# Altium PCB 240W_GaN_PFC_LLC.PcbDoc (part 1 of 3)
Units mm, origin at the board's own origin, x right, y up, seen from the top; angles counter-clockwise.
Board outline 105 x 71.8 mm, 4 copper layers (Top Layer, Layer 1, Layer 2, Bottom Layer), stack 1.787 mm thick; 165 components, 88 nets, 549 pads, 326 vias.
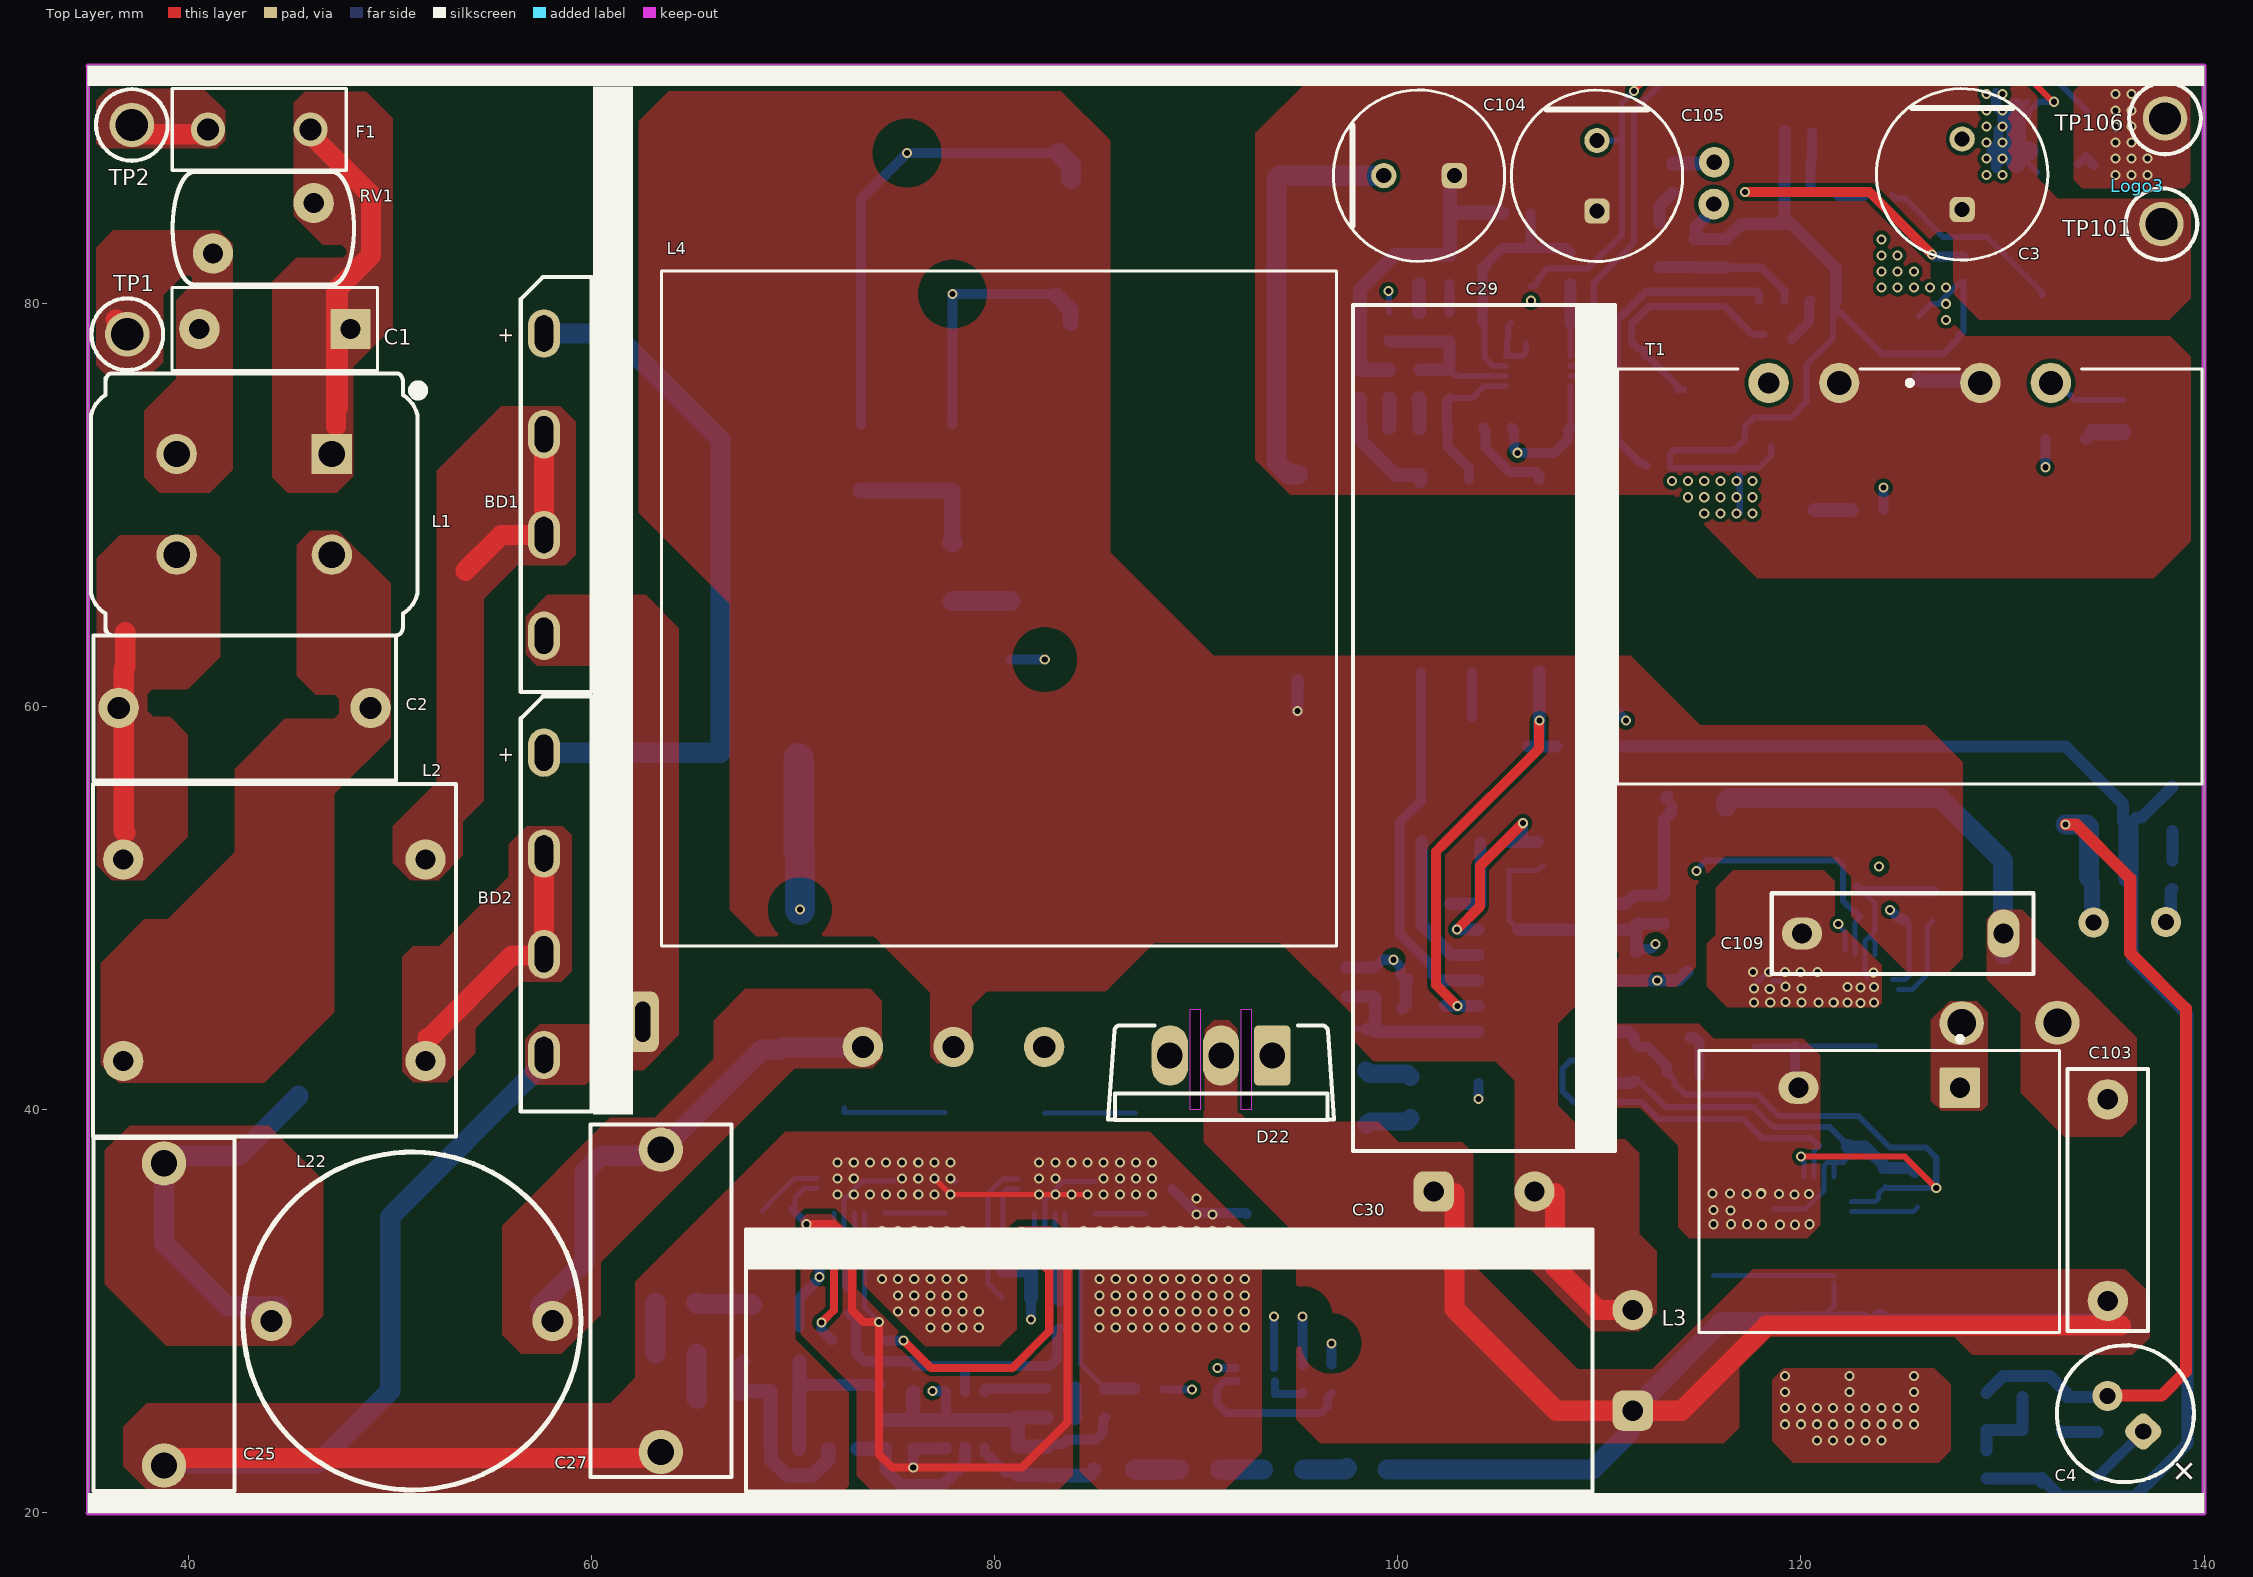
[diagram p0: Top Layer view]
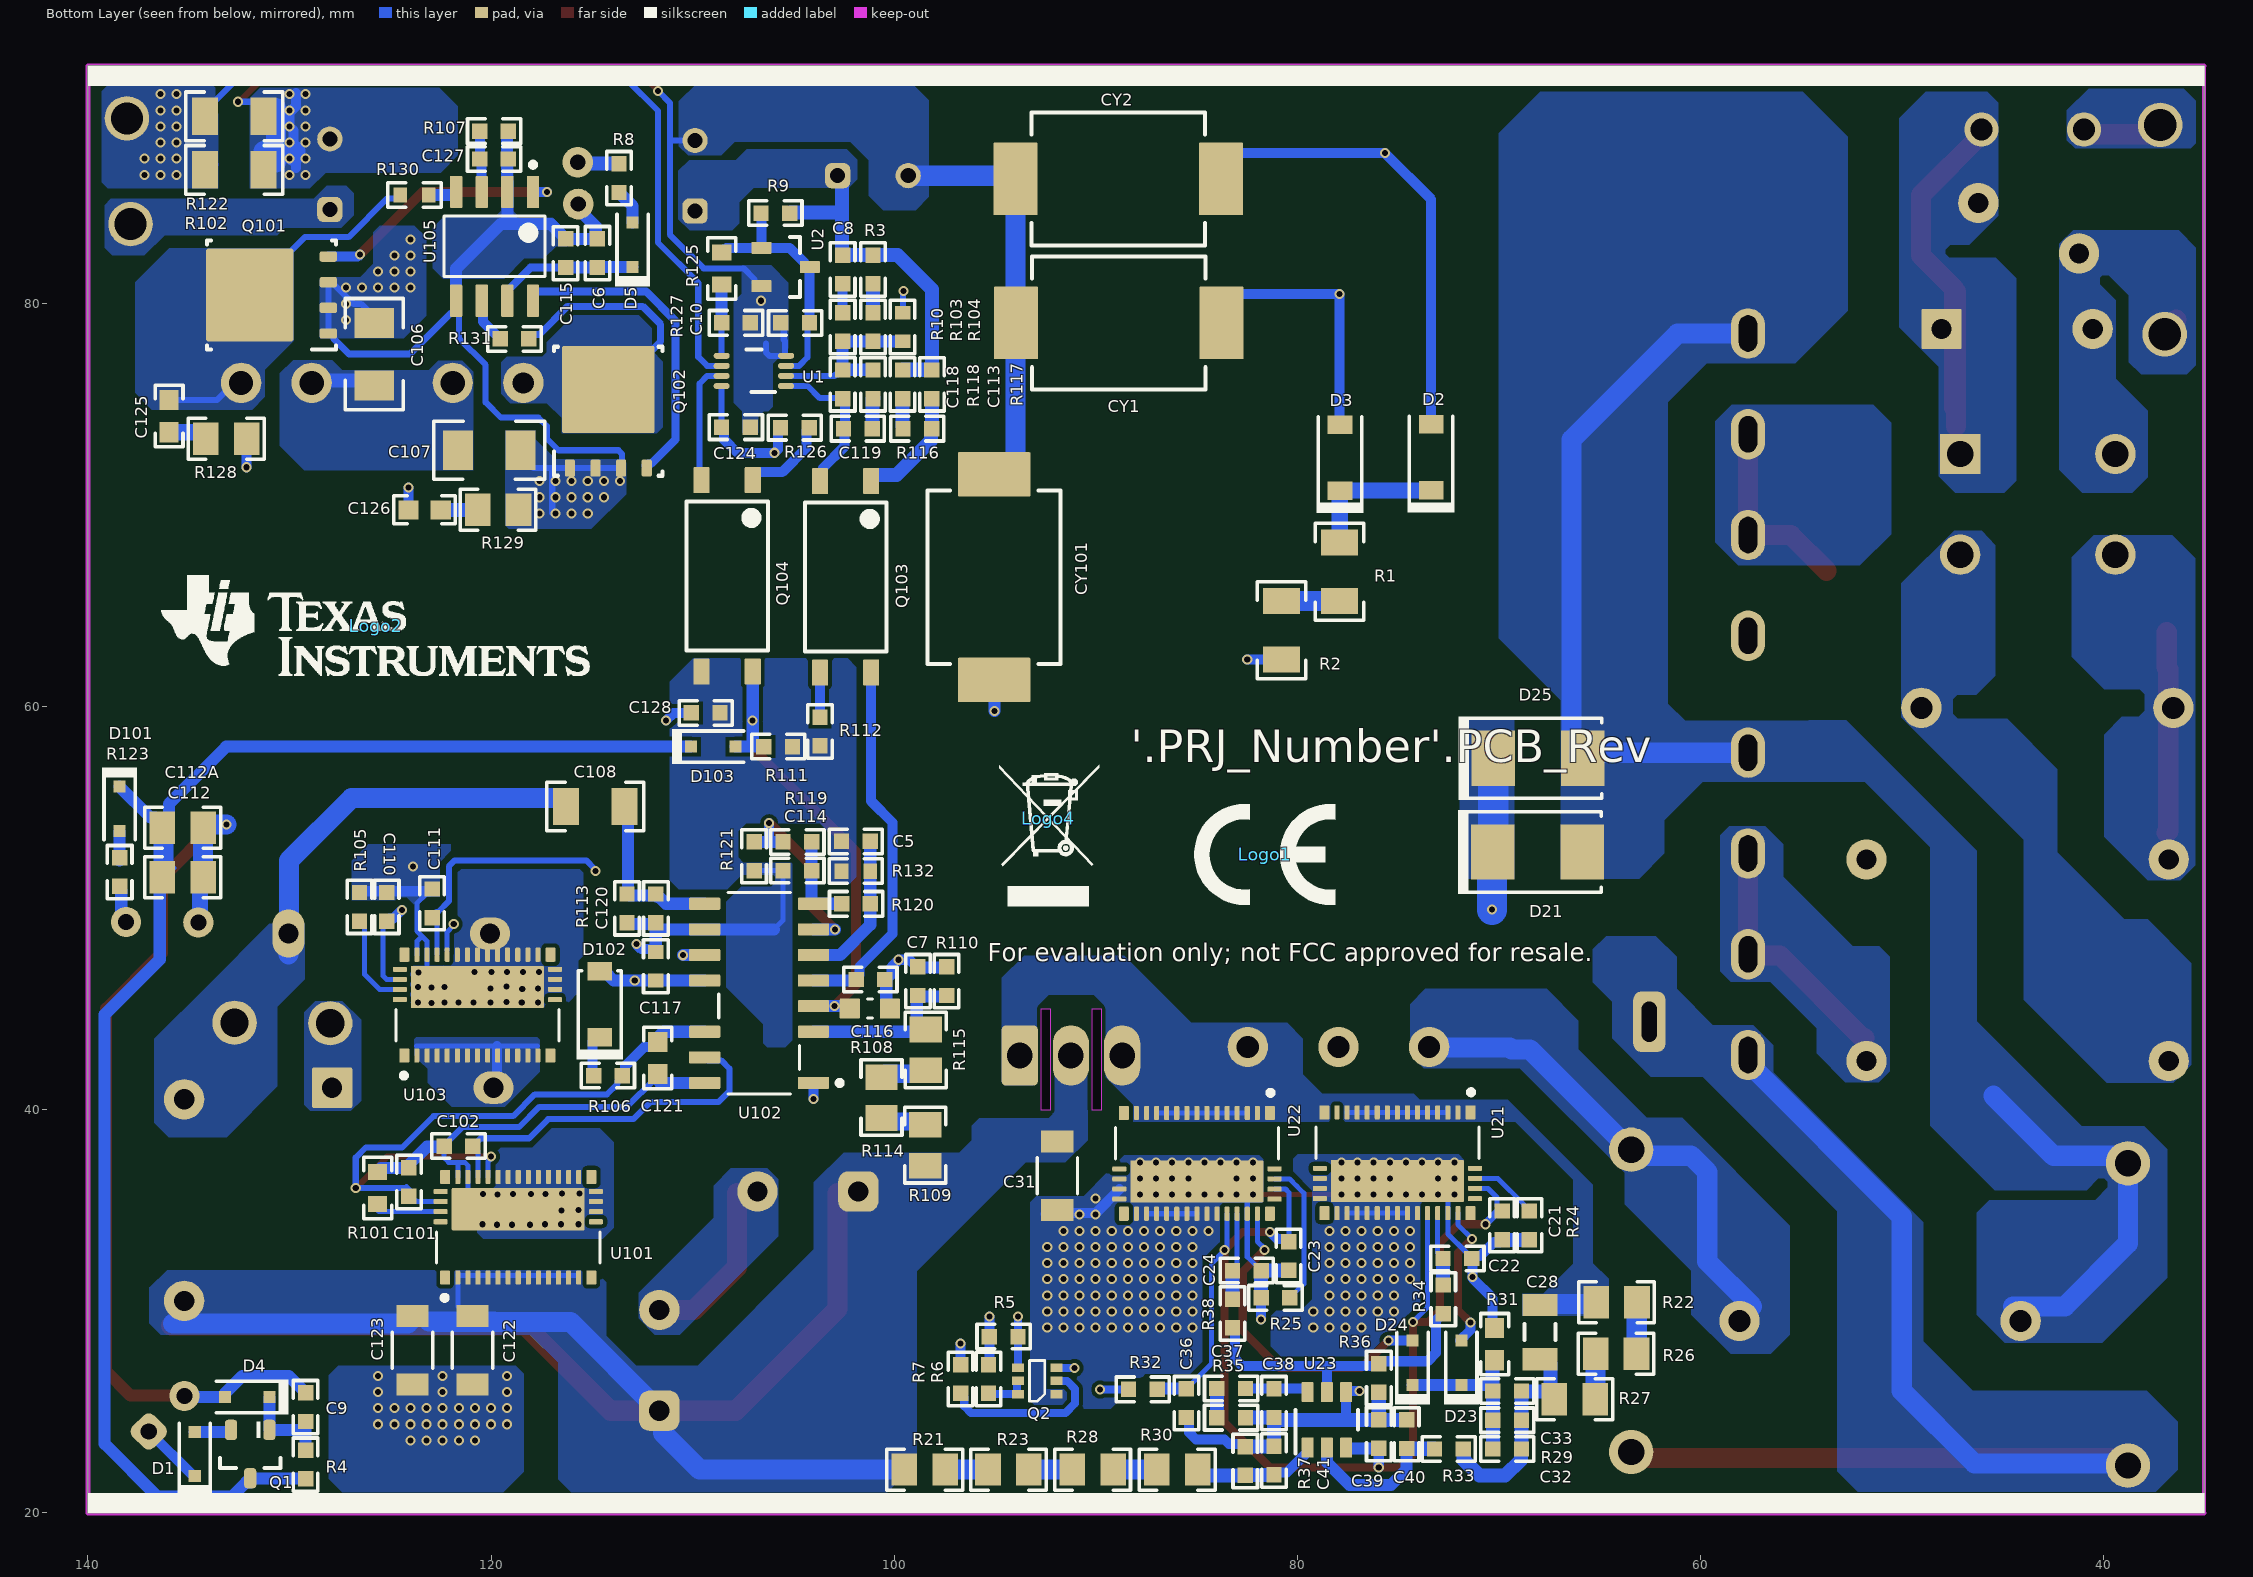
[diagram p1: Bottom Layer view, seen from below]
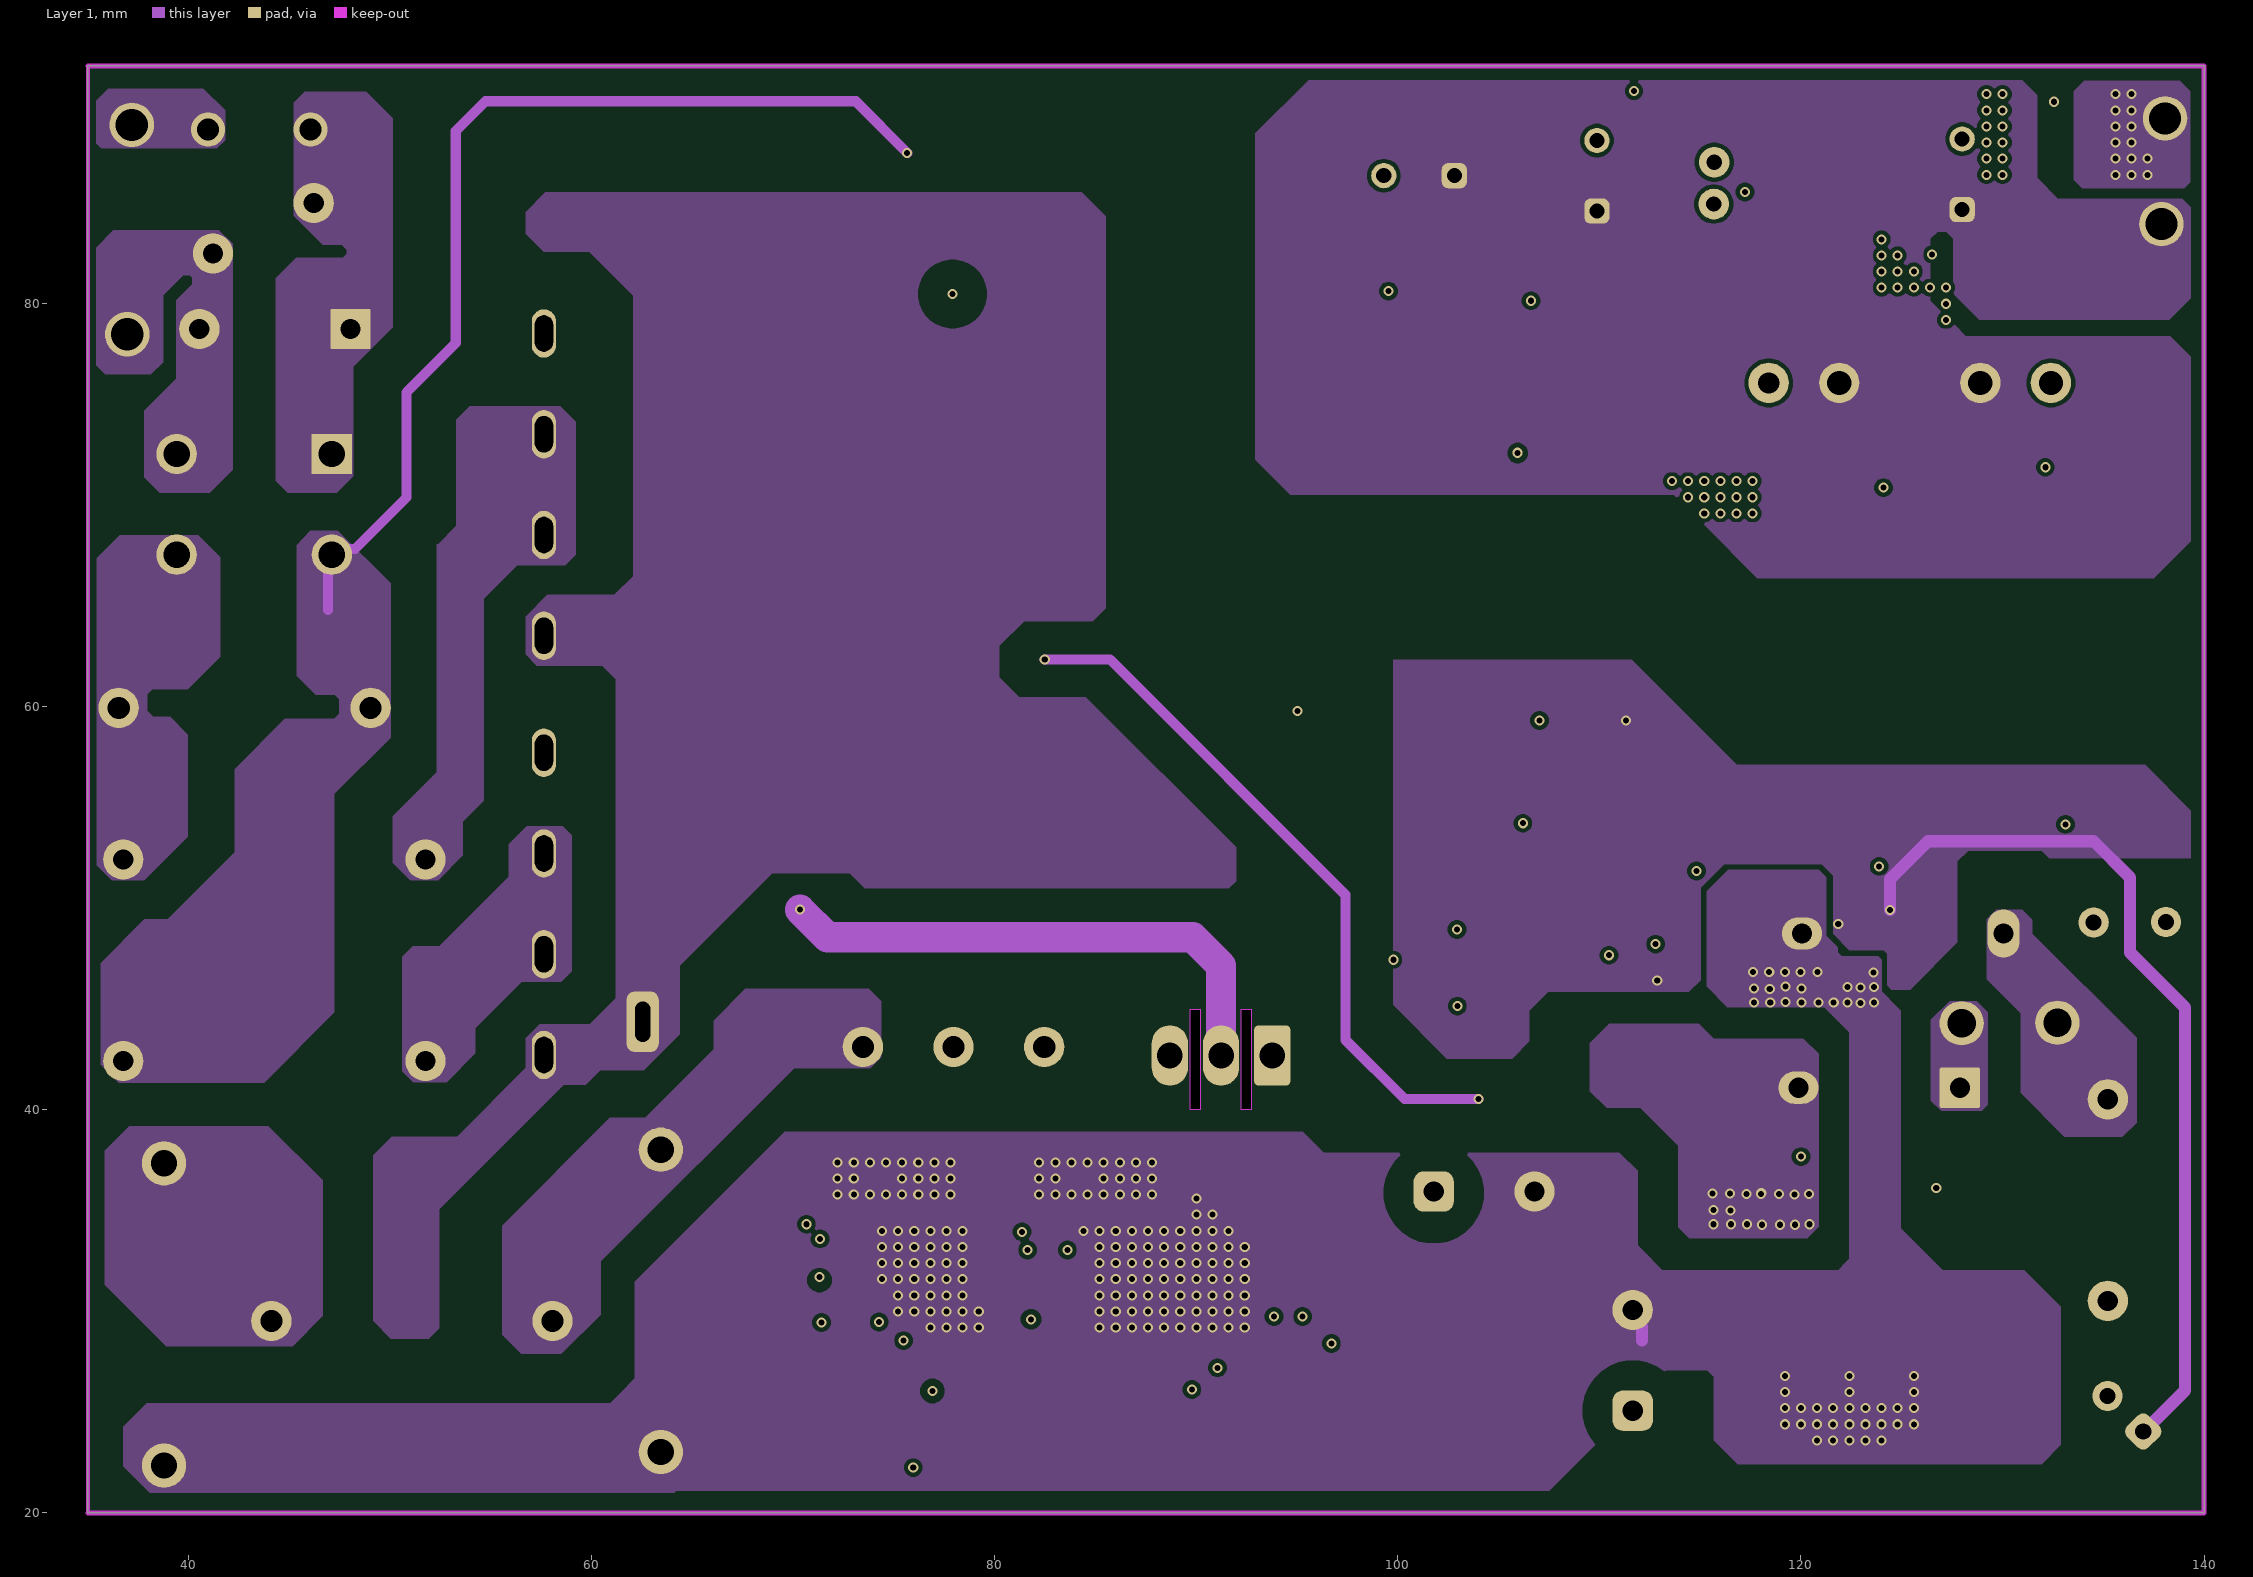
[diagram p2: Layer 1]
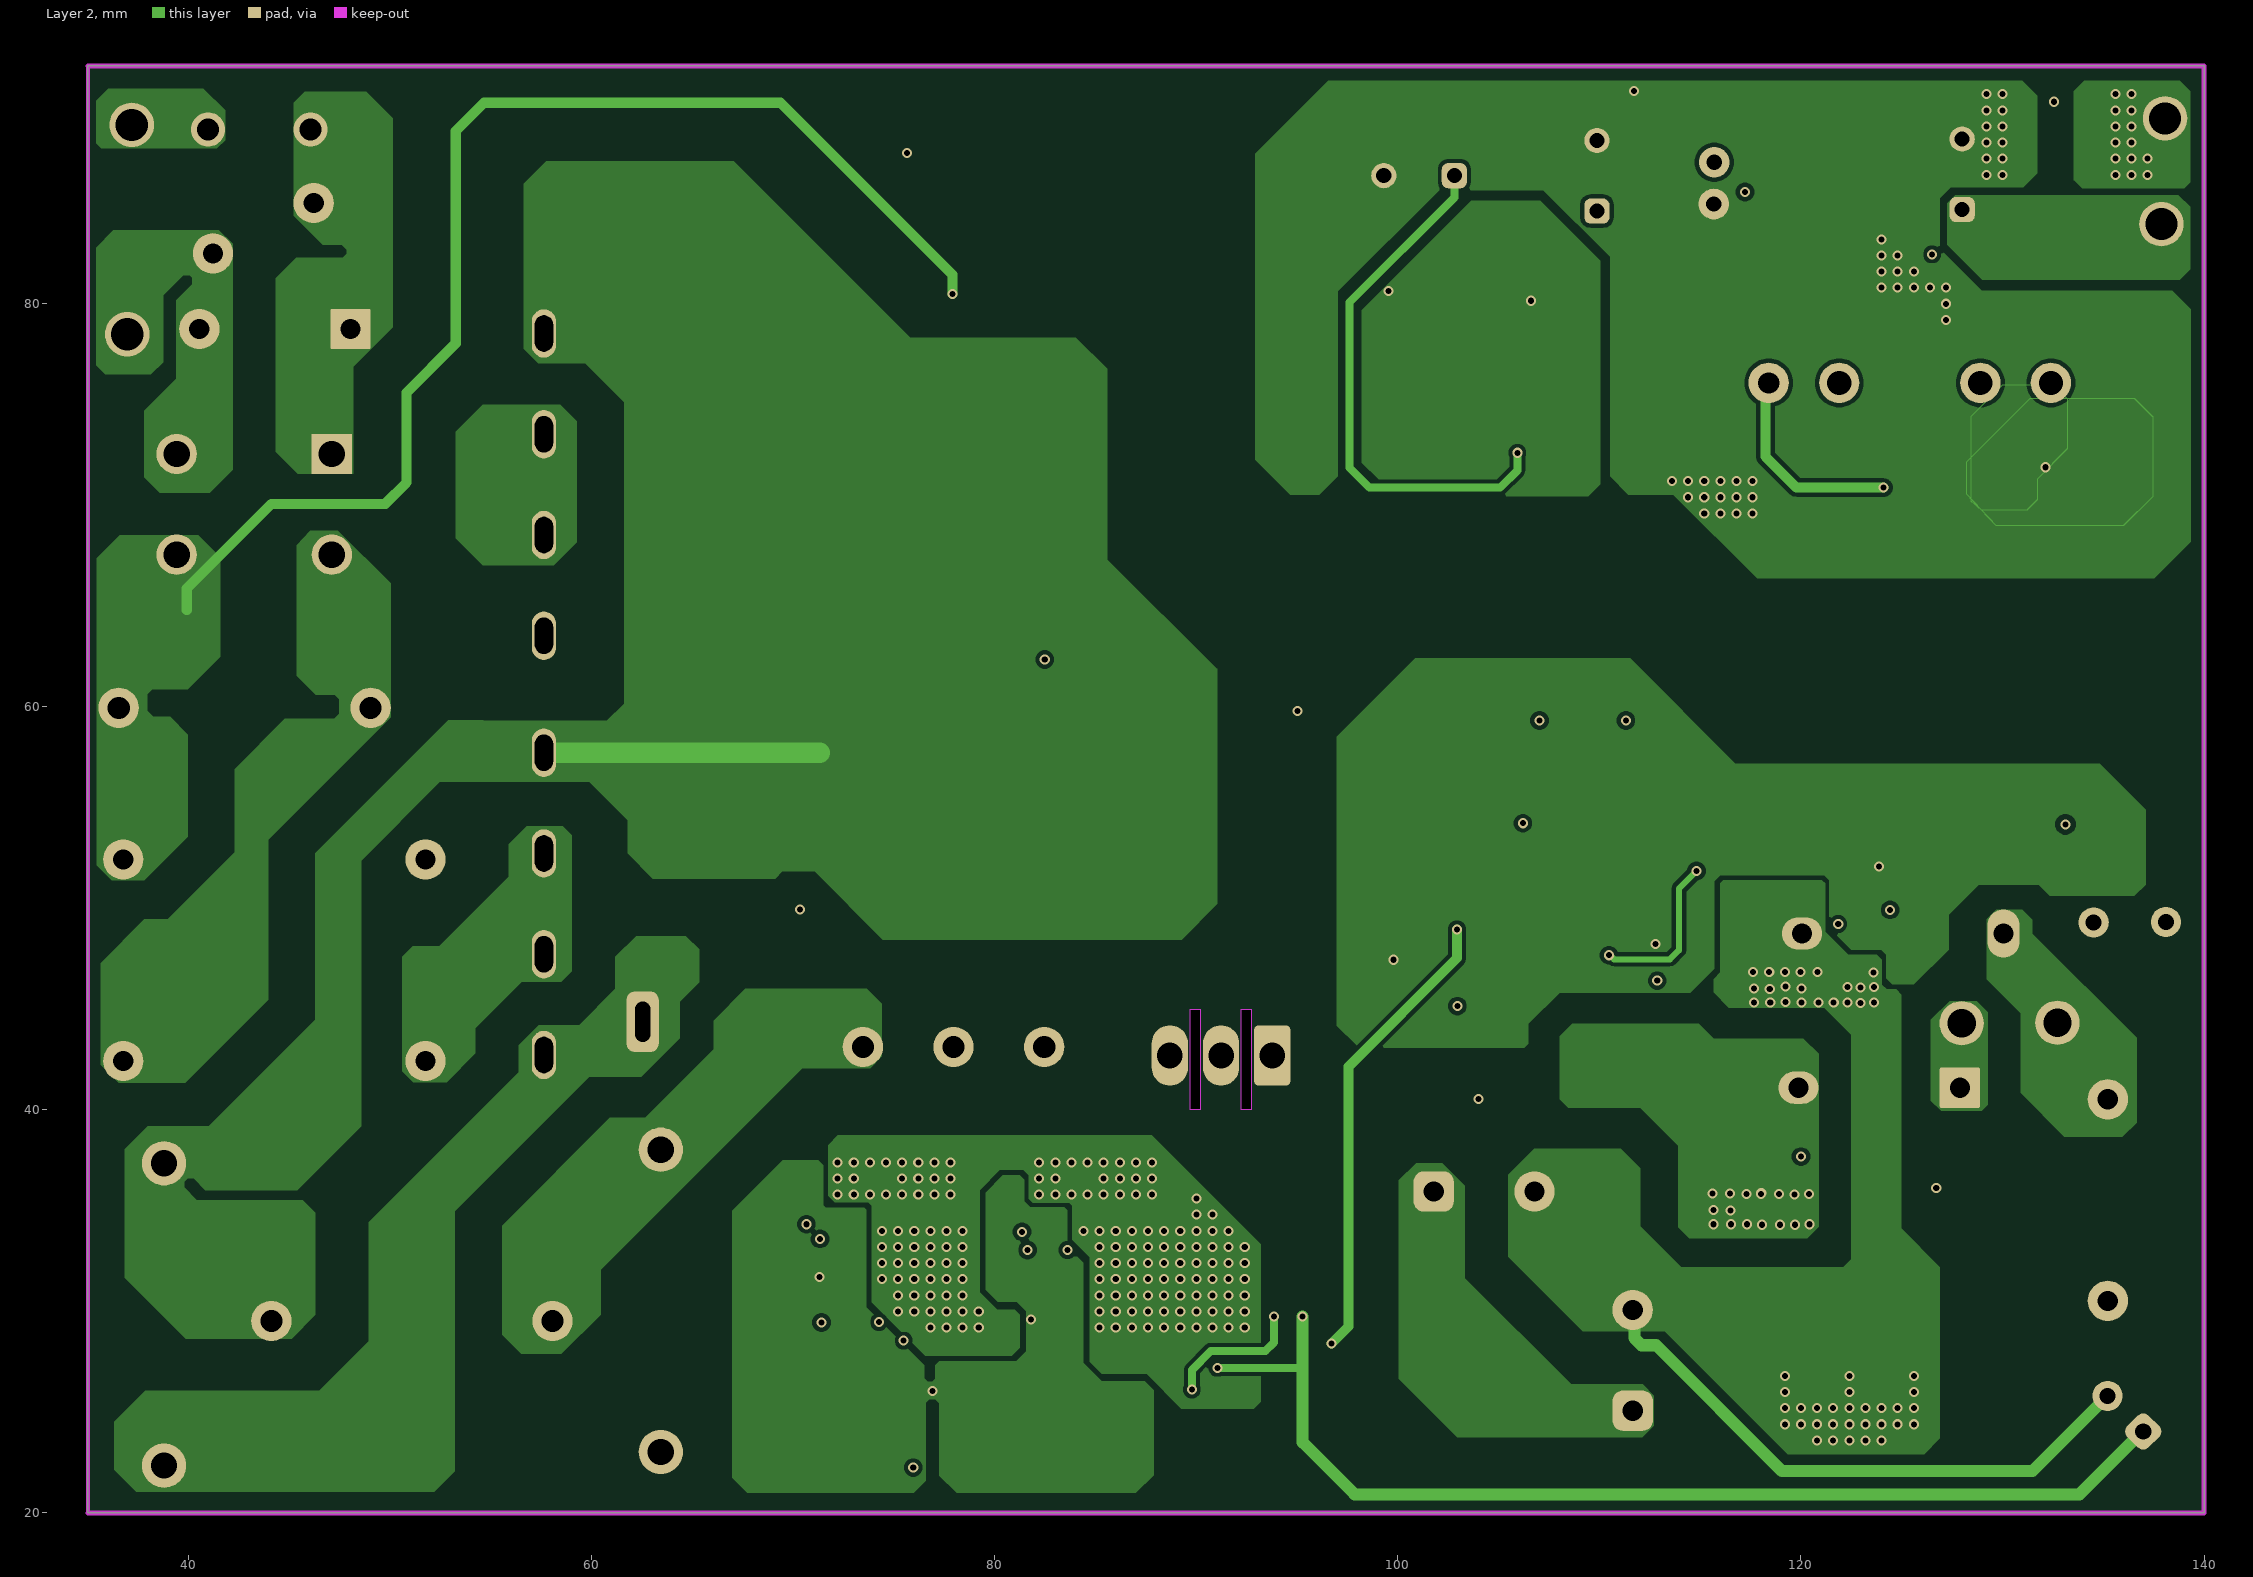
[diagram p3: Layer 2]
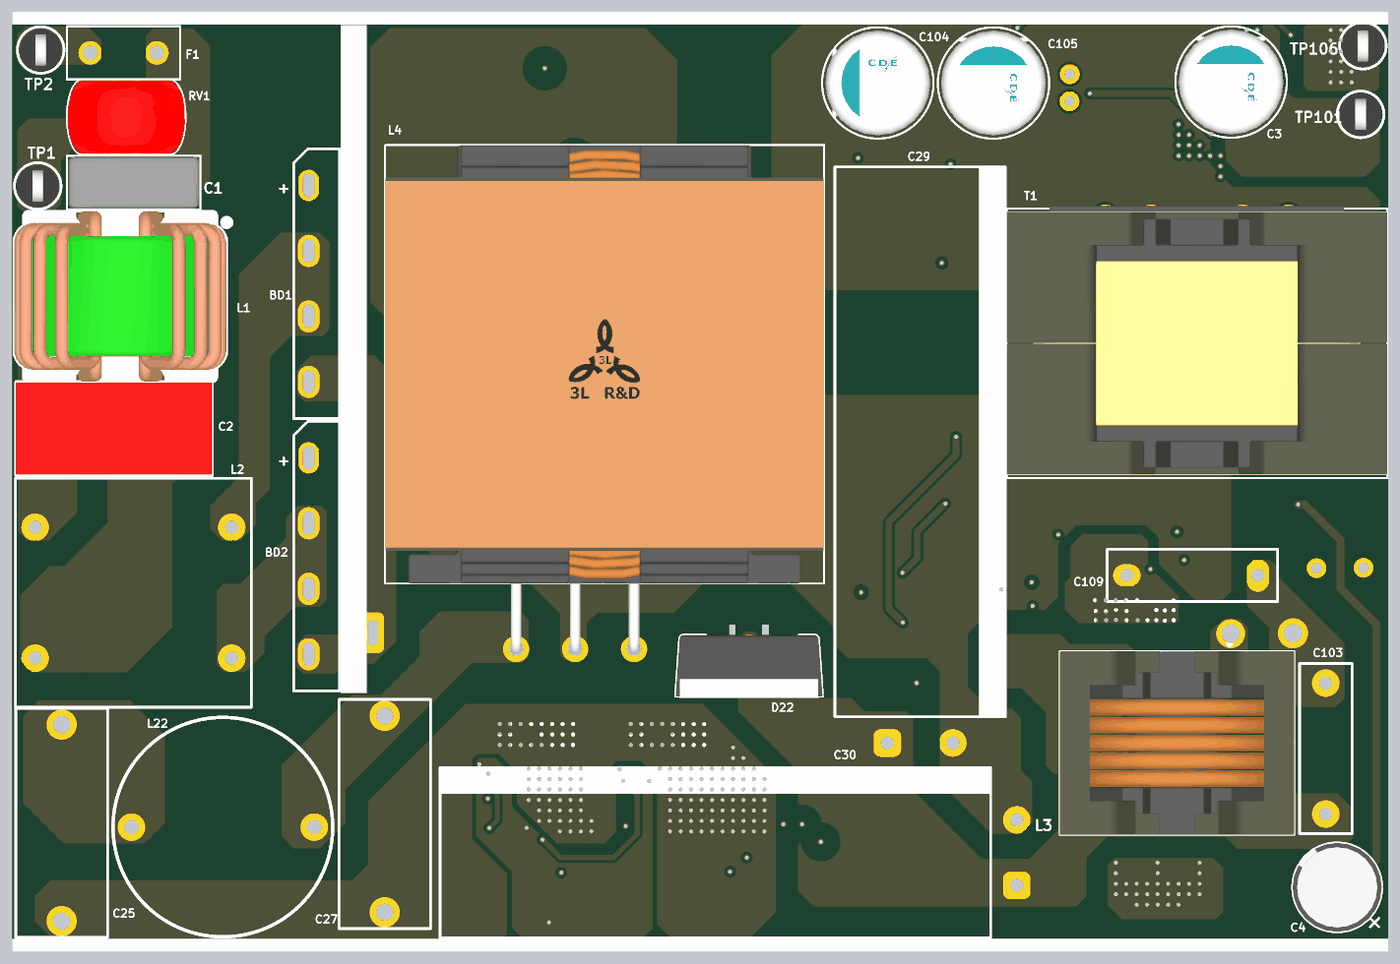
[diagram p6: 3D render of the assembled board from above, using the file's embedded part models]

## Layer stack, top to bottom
Top Solder: solder mask 0.0102, Solder Resist, Dk 3.5
Top Layer: signal copper 0.0356
Dielectric 1: prepreg 0.0711, PP-006, Dk 4.1
Layer 1: signal copper 0.035
Dielectric1: core 1.5037, FR-4 High Tg, Dk 4.8
Layer 2: signal copper 0.035
Dielectric 2: prepreg 0.0711, PP-006, Dk 4.1
Bottom Layer: signal copper 0.0356
Bottom Solder: solder mask 0.0102, Solder Resist, Dk 3.5

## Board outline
35,20 35,91.8 140,91.8 140,20
cut-out: 89.7,40 89.7,45 90.2,45 90.2,40
cut-out: 92.225,40 92.225,45 92.725,45 92.725,40

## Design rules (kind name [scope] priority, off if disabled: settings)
AcuteAngle [All] p1: minimum=4.50000000000000E+0001 checktracksonly=FALSE
AssemblyTestPointUsage [All] p1: valid=2
BoardOutlineClearance BoardOutlineClearance_MountingHoles [OnCopper and InComponentClass('Mounting Holes')] p1: gap=1 ignorepadtopadclearanceinfootprint=FALSE
BoardOutlineClearance BoardOutlineClearance_Poly [OnCopper and IsPoly] p2: gap=0.635 ignorepadtopadclearanceinfootprint=FALSE
BoardOutlineClearance [OnCopper and Not InComponentClass('Logo') and not InComponentClass('FiducialMark') and not InRegion(1000,500,4000,800) and not InPoly] p3: gap=0.508 ignorepadtopadclearanceinfootprint=FALSE
Clearance Clearance_Keepouts [((IsTrack Or IsArc) And Not InPoly) And IsFree and IsKeepOut vs ((IsTrack Or IsArc) And Not InPoly) And IsFree and IsKeepOut] p1: gap=0.5 ignorepadtopadclearanceinfootprint=FALSE
Clearance Clearance_Poly [InPolygon] p2: gap=0.2 ignorepadtopadclearanceinfootprint=TRUE
Clearance Clearance_FiducialMark [IsKeepOut and InComponentClass('FiducialMark') vs IsPad and InComponentClass('FiducialMark')] p3: gap=0 ignorepadtopadclearanceinfootprint=FALSE
Clearance [All] p4: gap=0.191 ignorepadtopadclearanceinfootprint=TRUE
ComponentClearance ComponentClearance_MountingHoles_FiducialMarks [InComponentClass('Mounting Holes') vs InComponentClass('FiducialMark')] p1: gap=1.27 collisioncheckmode=3 verticalgap=0.254 showdistances=FALSE
ComponentClearance ComponentClearance_Shunt [InComponentClass('Header') vs InComponentClass('Shunt')] p2: gap=0 collisioncheckmode=3 verticalgap=0 showdistances=FALSE
ComponentClearance ComponentClearance_Logo [InComponentClass('Logo')] p3: gap=0.762 collisioncheckmode=3 verticalgap=0.254 showdistances=FALSE
ComponentClearance ComponentClearance_ScrewToNut [(HasFootprint('NY PMS 440 0025 PH')) vs (HasFootprint('Keystone_1902C'))] p4: gap=0.127 collisioncheckmode=3 verticalgap=0.254 showdistances=FALSE
ComponentClearance ComponentClearance_MountingHoles [InComponentClass('Mounting Holes')] p5: gap=2.54 collisioncheckmode=3 verticalgap=2540 showdistances=FALSE
ComponentClearance ComponentClearance_SmallPassives [HasFootprint('0201*') or HasFootprint('0402*') or HasFootprint('0508') or HasFootprint('0603*') or HasFootprint('0612') or HasFootprint('0805*') or HasFootprint('0815*') or HasFootprint('0830*') or HasFootprint('1206*') or HasFootprint('1210*') or HasFootprint('1808*') or HasFootprint('1812*') or HasFootprint('1825*') or HasFootprint('2010*') or HasFootprint('2220*') or HasFootprint('2225*') or HasFootprint('2512*') or HasFootprint('2728*') or HasFootprint('3518*') vs HasFootprint('0201*') or HasFootprint('0402*') or HasFootprint('0508') or HasFootprint('0603*') or HasFootprint('0612') or HasFootprint('0805*') or HasFootprint('0815*') or HasFootprint('0830*') or HasFootprint('1206*') or HasFootprint('1210*') or HasFootprint('1808*') or HasFootprint('1812*') or HasFootprint('1825*') or HasFootprint('2010*') or HasFootprint('2220*') or HasFootprint('2225*') or HasFootprint('2512*') or HasFootprint('2728*') or HasFootprint('3518*')] p6: gap=0.38 collisioncheckmode=3 verticalgap=0.254 showdistances=FALSE
ComponentClearance ComponentClearance_THtoSMT [IsThruComponent vs IsSMTComponent] p7: gap=0.457 collisioncheckmode=3 verticalgap=0.762 showdistances=FALSE
ComponentClearance ComponentClearance_THtoTH [IsThruComponent vs IsThruComponent] p8: gap=0.508 collisioncheckmode=3 verticalgap=0.762 showdistances=FALSE
ComponentClearance [All] p9: gap=0.457 collisioncheckmode=3 verticalgap=0.254 showdistances=FALSE
DiffPairsRouting [All] p1: maxlimit=2.54 minlimit=0.254 mostfreqgap=0.254 toplayer_minwidth=0.381 toplayer_maxwidth=0.381 toplayer_prefwidth=0.381 midlayer1_minwidth=0.381 midlayer1_maxwidth=0.381 midlayer1_prefwidth=0.381 midlayer2_minwidth=0.381 midlayer2_maxwidth=0.381 midlayer2_prefwidth=0.381 bottomlayer_minwidth=0.381 bottomlayer_maxwidth=0.381 bottomlayer_prefwidth=0.381 maxuncoupledlength=25.4
FabricationTestPointUsage TestPointUsage [All] p1: valid=2 allowmultiple=FALSE
FabricationTestpoint Testpoint [All] p1: side=3 testpointundercomponent=TRUE minsize=1.016 maxsize=2.54 preferedsize=1.524 minholesize=0 maxholesize=1.016 preferedholesize=0.813 testpointgrid=0.025 allowsidetop=TRUE allowsidebottom=TRUE usegrid=TRUE gridtolerance=0
FanoutControl Fanout_LCC [IsLCC] p1: bgadir=Out bgaviamode=Centered fanoutstyle=Auto fanoutdirection=Alternating viagrid=0.025 // Fanout_LCC (Default Rule)
FanoutControl Fanout_BGA [IsBGA] p2: bgadir=Out bgaviamode=Centered fanoutstyle=Auto fanoutdirection=Alternating viagrid=0.025 // Fanout_BGA (Default Rule)
FanoutControl Fanout_Default [All] p4: bgadir=Out bgaviamode=Centered fanoutstyle=Auto fanoutdirection=Alternating viagrid=0.025 // Fanout_Default (Default Rule)
FanoutControl Fanout_Small [(CompPinCount < 5)] p5: bgadir=Out bgaviamode=Centered fanoutstyle=Auto fanoutdirection=OutThenIn viagrid=0.025 // Fanout_Small (Default Rule)
HoleSize [All] p1: absolutevalues=TRUE maxlimit=6.375 minlimit=0.2 maxpercent=80.000 minpercent=20.000
MinimumAnnularRing MinimumAnnularRing_ThermalPadVias [IsVia and InAnyComponent] p1: minimumring=0.1
MinimumAnnularRing [All] p2: minimumring=0.1
MinimumSolderMaskSliver MinimumSolderMaskSliver_Logo [InComponentClass('Logo') vs InComponentClass('Logo')] p1: minsoldermaskwidth=0.018
MinimumSolderMaskSliver [All] p2: minsoldermaskwidth=0.1
PlaneConnect [All] p1: planeconnectstyle=Direct reliefexpansion=0.254 reliefentries=4 reliefconductorwidth=0.254 reliefairgap=0.254
PolygonConnect [All] p1: connectstyle=Direct reliefconductorwidth=0.254 reliefentries=4 polygonreliefangle="90 Angle" airgapwidth=0.254
RoutingVias ThermalPadVias [IsVia and InAnyComponent] p1: holewidth=0.2 width=0.5 viastyle="Through Hole" minholewidth=0.2 minwidth=0.5 maxholewidth=0.33 maxwidth=0.6
RoutingVias [All] p2: holewidth=0.406 width=0.864 viastyle="Through Hole" minholewidth=0.2 minwidth=0.61 maxholewidth=1.016 maxwidth=1.651
SilkToBoardRegionClearance [Not ((IsComment or IsDesignator) And (Hide <> 'False')) and not InRegion(1000,500,4000,800)] p1:
SilkToSilkClearance SilkToSilkClearance_Pb-FreeLogo [(HasFootprint('Pb-Free_Overlay_Medium') OR HasFootprint('Pb-Free_Overlay_Small')) vs (HasFootprint('Pb-Free_Overlay_Medium') OR HasFootprint('Pb-Free_Overlay_Small'))] p1: silktosilkclearance=0
SilkToSilkClearance [All] p2: silktosilkclearance=0.1
SilkToSolderMaskClearance SilkToComponentPadClearance [(IsPad or IsFill or IsRegion) and InAnycomponent] p1: minsilkscreentomaskgap=0.127 clearancetoexposedcopper=TRUE
SilkToSolderMaskClearance "Silk to Solder Mask Opening" [All] p2: minsilkscreentomaskgap=0.1 clearancetoexposedcopper=FALSE
SolderMaskExpansion [All] p1: expansion=0.05 istentingtop=FALSE
UnRoutedNet [All] p1: checkbadconnections=TRUE
Width [All] p1: maxlimit=2.54 minlimit=0.152 preferedwidth=0.254 checkconnectedcopper=TRUE
14 further rules are at their usual default settings.

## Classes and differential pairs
component class 240W_PFC_Stage: C21 C22 C23 C24 C25 C27 C28 C29 C30 C31 C32 C33 C36 C37 C38 C39 C40 C41 D21 D22 D23 D24 D25 L4 L22 Q2 R5 R6 R7 R21 R22 R23 R24 R25 R26 R27 R28 R29 R30 R31 R32 R33 R34 R35 R36 R37 R38 U21 U22 U23
component class 240W_LLC_Stage: C3 C4 C5 C6 C7 C8 C9 C10 C101 C102 C103 C104 C105 C106 C107 C108 C109 C110 C111 C112 C112A C113 C114 C115 C116 C117 C118 C119 C120 C121 C122 C123 C124 C125 C126 C127 C128 CY101 D1 D4 D5 D101 D102 D103 L3 Q1 Q101 Q102 Q103 Q104 R3 R4 R8 R9 R10 R101 R102 R103 R104 R105 R106 R107 R108 R109 R110 R111 R112 R113 R114 R115 R116 R117 R118 R119 R120 R121 R122 R123 R125 R126 R127 R128 R129 R130 R131 R132 T1 TP101 TP106 U1 U2 U101 U102 U103 U105
component class Logo: Logo2
component class 240W_GaN_PFC_LLC_AC_EMI: BD1 BD2 C1 C2 CY1 CY2 D2 D3 F1 L1 L2 Logo1 Logo2 Logo3 Logo4 R1 R2 RV1 TP1 TP2

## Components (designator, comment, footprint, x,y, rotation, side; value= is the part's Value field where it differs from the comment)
BD1 "GBL610" GBL610 60.025,71.027 r270 top locked
BD2 "GBL610" GBL610 60.025,50.225 r270 top locked
C1 "R413D1100JMT0K" FP-R413D1100JMT0K_RADIAL-MFG 44.275,78.75 r180 top value=1nF
C2 "890324024002" WCAP-FTX2_1500x700x1250 42.775,59.95 r0 top locked value=0.22uF
C3 "227AVG035MFBJ" FP-227AVG035MFBJ_RADIAL-MFG 128,86.425 r270 top locked value=220µF
C4 "35ZLJ100M6.3X11" Rubycon_630x1100 136.1,24.925 r135 top locked value=100uF
C5 "C0603C331K5RACTU" 0603_HV#1 101.9,53.325 r0 bottom value=330pF
C6 "GRM188R61E106KA73D" 0603_HV#1 114.725,82.514 r90 bottom value=10uF
C7 "C0603C103K5RACTU" 0603_HV#1 98.819,46.391 r90 bottom value=0.01uF
C8 "06035A471JAT2A" 0603_HV#1 102.55,81.7 r270 bottom value=470pF
C9 "GCM188R71H104KA57D" 0603_HV#1 129.2,25.25 r90 bottom value=0.1uF
C10 "06035C104KAZ2A" 0603_HV#1 104.911,79.05 r0 bottom value=0.1uF
C21 "GRJ188R71E105KE11D" 0603_HV#1 69.825,34.275 r90 bottom value=1uF
C22 "CGA3E2C0G1H220J080AA" 0603_HV#1 72.05,32.625 r180 bottom value=22pF
C23 "GRJ188R71E105KE11D" 0603_HV#1 80.425,32.75 r90 bottom value=1uF
C24 "CGA3E2C0G1H220J080AA" 0603_HV#1 82.5,32.025 r180 bottom value=22pF
C25 "1uF/450V" C_film_17.5x7 38.775,29.85 r270 top locked
C27 "1uF/450V" C_film_17.5x7 63.425,30.525 r270 top locked
C28 "VJ1206A100JXGAT5Z" 1206L 67.95,28.975 r270 bottom value=10pF
C29 "82uF" Cap_12.5x40_H1 104.275,35.95 r90 top locked
C30 "82uF" Cap_12.5x40_H1 111.65,27.575 r180 top locked
C31 "C3216X7T2W104K160AE" 1206_180 91.9,36.725 r270 bottom value=0.1uF
C32 "GRM1885C1H332JA01D" 0603_HV#1 69.575,23.175 r0 bottom value=3300pF
C33 "GRM1885C1H221JA01D" 0603_HV#1 69.575,26.05 r0 bottom value=220pF
C36 "GCM188R71H224KA64D" 0603_HV#1 85.495,25.45 r270 bottom value=0.22uF
C37 "06033C105KAT2A" 0603_HV#1 83.275,26.175 r0 bottom value=1uF
C38 "GRM188R71H333KA61D" 0603_HV#1 81.15,25.45 r270 bottom value=0.033uF
C39 "06033C105KAT2A" 0603_HV#1 75.948,23.913 r90 bottom value=1uF
C40 "C0603C391J5GACTU" 0603_HV#1 74.564,23.906 r90 bottom value=390pF
C41 "C0603C222K5RACTU" 0603_HV#1 81.15,22.6 r90 bottom value=2200pF
C101 "06035C104KAZ2A" 0603_HV#1 124.075,36.425 r90 bottom value=0.1uF
C102 "CGA3E2C0G1H220J080AA" 0603_HV#1 121.614,38.2 r0 bottom value=22pF
C103 "PHE426MA5150JR05" PHE426_1300x400x900#1 135.225,35.525 r90 top value=0.015uF
C104 "227AVG035MFBJ" FP-227AVG035MFBJ_RADIAL-MFG 101.05,86.356 r0 top locked value=220µF
C105 "227AVG035MFBJ" FP-227AVG035MFBJ_RADIAL-MFG 109.875,86.35 r270 top locked value=220µF
C106 "CL31B106KBHNNNE" 1206_180M 125.8,77.5 r90 bottom value=10uF
C107 "CL31B106KBHNNNE" 1206_180M 120.09,72.732 r180 bottom value=10uF
C108 "GRM31A5C2J151JW01D" 1206 114.825,55.051 r180 bottom value=150pF
C109 "PHE426MA5150JR05" PHE426_1300x400x900#2 125.05,48.75 r180 top value=0.015uF
C110 "06035C104KAZ2A" 0603_HV#1 125.175,50.075 r90 bottom value=0.1uF
C111 "CGA3E2C0G1H220J080AA" 0603_HV#1 122.925,50.25 r90 bottom value=22pF
C112 "C2012X5R1V156M125AC" 0805_HV 135.3,51.55 r180 bottom value=15uF
C112A "C2012X5R1V156M125AC" 0805_HV 135.3,54 r180 bottom value=15uF
C113 "C0603C472K5RACTU" 0603_HV#1 99.575,76 r270 bottom value=4700pF
C114 "GRM188Z71A475ME15D" 0603_HV#1 104.8,51.874 r0 bottom value=4.7uF
C115 "C1608X7R1V105K080AC" 0603_HV#1 116.3,82.511 r90 bottom value=1uF
C116 "GRM188R71H152KA01D" 0603_HV#1 101.175,46.467 r180 bottom value=1500pF
C117 "GRJ188R71E105KE11D" 0603_HV#2 111.825,47.125 r270 bottom value=1uF
C118 "06035A181JAT2A" 0603_HV#1 102.55,76 r270 bottom value=180pF
C119 "C1608X7R1H473K080AA" 0603_HV#1 101.8,73.8 r0 bottom value=0.047uF
C120 "GRM1885C1H221JA01D" 0603_HV#1 111.825,50 r270 bottom value=220pF
C121 "C0603C101F5GACTU" 0603#1 111.725,42.575 r90 bottom value=100pF
C122 "C1206C223KDRACTU" 1206_190 120.925,28.075 r270 bottom value=0.022uF
C123 "C1206C223KDRACTU" 1206_190 123.9,28.075 r270 bottom value=0.022uF
C124 "C0603C104K5RACTU" 0603_HV#1 107.85,73.875 r180 bottom value=0.1uF
C125 "C1608C0G2A101F080AA" 0603#1 135.975,74.425 r90 bottom value=100pF
C126 "C1608C0G2A101F080AA" 0603#1 123.297,69.775 r0 bottom value=100pF
C127 "C0603X102K5RACTU" 0603_HV#1 119.849,87.187 r0 bottom value=1000pF
C128 "GRJ188R71E105KE11D" 0603_HV#1 109.35,59.7 r0 bottom value=1uF
CY1 "DK1E3EA102M86RAH01" DK1_86 88.85,79.05 r0 bottom value=1000pF
CY2 "DK1E3EA102M86RAH01" DK1_86 88.875,86.2 r0 bottom value=1000pF
CY101 "DK1E3EA102M86RAH01" DK1_86 95.035,66.436 r270 bottom value=1000pF
D1 "SD103AWS-TP" SOD-323 134.7,22.925 r90 bottom value=40V
D2 "S1MFL" SOD-123 73.35,72.375 r90 bottom value=1000V
D3 "S1MFL" SOD-123 77.875,72.362 r90 bottom value=1000V
D4 "MMSZ5248BS-7-F" SOD-323 132.1,25.75 r0 bottom value=18V
D5 "SD103AWS-TP" SOD-323 112.975,82.925 r90 bottom value=40V
D21 "S3MB-13-F" SMB 68.075,52.8 r180 bottom value=1000V
D22 "BYV34G-600,127" TO-220AB 91.225,42.7 r180 top locked value=600V
D23 "1N4148WS-7-F" SOD-323 71.85,27.45 r90 bottom value=75V
D24 "1N4148WS-7-F" SOD-323 74.275,27.45 r90 bottom value=75V
D25 "S3MB-13-F" SMB 68.05,57.45 r180 bottom value=1000V
D101 "1N4148WS-7-F" SOD-323 138.431,54.94 r270 bottom value=75V
D102 "UFM15PL-TP" SOD-123FL 114.6,45.237 r90 bottom value=600V
D103 "MM3Z27VST1G" SOD-323 108.975,58.025 r180 bottom value=27V
F1 "39213150000" FUSE_392 43.5,88.65 r180 top locked
L1 "744842565" WE-CMB_NiZn_S 43.25,70.05 r270 top
L2 "DCN181713H-222HF" CM_DCN181713H 44.25,47.425 r90 top locked
L3 "G244038LF" FP-G244038LF_PTH2-MFG 123.88,35.95 r180 top locked value=43uH
L4 "ATQ32-T-105UH-W2" FP-202410103L250W_PTH3-MFG 80.2,64.875 r0 top locked value=105uH
L22 "TCX2-750K-3.5A-127125-U" L_Ring_H_D=16.76mm 51.075,29.525 r0 top locked
Logo1 "CE Mark" CE_Mark_5mm 81.6,52.675 r180 bottom
Logo2 "Texas Instruments" TI_Stacked_Overlay_Small 125.725,64.025 r180 bottom
Logo3 "FCC disclaimer" FCC_disclaimer 136.69,85.852 r0 top
Logo4 "WEEE logo" WEEE_Minimum 92.35,54.475 r180 bottom
Q1 "2N7002-7-F" SOT-23 131.95,22.925 r270 bottom value=60V
Q2 "DMN63D8LDW-7" SOT-363 92.9,26.55 r0 bottom value=30V
Q101 "CSD18540Q5B" DNK0008A 130.895,80.435 r0 bottom value=60V
Q102 "CSD18540Q5B" DNK0008A 114.181,74.667 r90 bottom value=60V
Q103 "TLP383(GR-TPL,E" FP-TLP383(GR-TPL,E_SO6-4-MFG 102.408,66.45 r270 bottom
Q104 "TLP383(GR-TPL,E" FP-TLP383(GR-TPL,E_SO6-4-MFG 108.283,66.5 r270 bottom
R1 "CRCW12062K20JNEA" 1206 77.9,66.7 r90 bottom value=2.2k
R2 "CRCW12062K20JNEA" 1206 80.775,63.8 r90 bottom value=2.2k
R3 "RC0603JR-070RL" 0603_HV#1 101.05,81.7 r90 bottom value=0
R4 "CRCW0603100KJNEAC" 0603_HV#1 129.2,22.4 r270 bottom value=100k
R5 "RCS06030000Z0EA" 0603_HV#1 94.564,28.75 r180 bottom value=0
R6 "CRCW0603510KJNEA" 0603_HV#1 95.317,26.644 r90 bottom value=510k
R7 "RCS06030000Z0EA" 0603_HV#1 96.7,26.65 r270 bottom value=0
R8 "CRCW06034R70JNEA" 0603_HV#1 113.65,86.236 r270 bottom value=4.7
R9 "CRCW060320K0FKEA" 0603_HV#1 105.891,84.499 r180 bottom value=20.0k
R10 "CRCW060310K0JNEA" 0603_HV#1 102.55,78.85 r90 bottom value=10k
R21 "CRCW08052M74FKEA" 0805_HV 98.475,22.15 r0 bottom value=2.74Meg
R22 "CRCW08053M24FKEA" 0805_HV 64.15,30.45 r0 bottom value=3.24Meg
R23 "CRCW08052M74FKEA" 0805_HV 94.325,22.15 r0 bottom value=2.74Meg
R24 "CRCW0603150KJNEA" 0603_HV#1 68.475,34.275 r90 bottom value=150k
R25 "CRCW0603150KJNEA" 0603_HV#1 81.075,30.675 r180 bottom value=150k
R26 "CRCW08053M24FKEA" 0805_HV 64.175,27.9 r180 bottom value=3.24Meg
R27 "CRCW08053M24FKEA" 0805_HV 66.225,25.647 r180 bottom value=3.24Meg
R28 "CRCW08052M74FKEA" 0805_HV 90.15,22.15 r0 bottom value=2.74Meg
R29 "RC0603FR-0724K3L" 0603_HV#1 69.575,24.6 r180 bottom value=24.3k
R30 "CRCW08051M82FKEA" 0805_HV 85.95,22.15 r0 bottom value=1.82Meg
R31 "RC0603FR-0764R9L" 0603#1 70.2,28.375 r270 bottom value=64.9
R32 "CRCW060320R0JNEA" 0603_HV#1 87.658,26.137 r0 bottom value=20
R33 "RC0603JR-07750RL" 0603_HV#1 72.475,23.175 r180 bottom value=750
R34 "CRCW060347R0JNEA" 0603_HV#1 72.75,30.6 r90 bottom value=47
R35 "CRCW0603180KJNEA" 0603_HV#1 83.275,24.725 r0 bottom value=180k
R36 "CRCW0603220KJNEA" 0603_HV#1 75.95,26.7 r90 bottom value=220k
R37 "RC0603FR-0766K5L" 0603_HV#1 82.575,22.575 r270 bottom value=66.5k
R38 "CRCW060347R0JNEA" 0603_HV#1 83.211,29.895 r270 bottom value=47
R101 "CRCW0603150KJNEA" 0603#2 125.625,36.125 r270 bottom value=150k
R102 "CSNL1206FT3L00" 1206 132.739,86.645 r0 bottom value=0.003
R103 "RC0603FR-07220KL" 0603_HV#1 101.05,78.85 r90 bottom value=220k
R104 "RC0603FR-0725K5L" 0603_HV#3 99.575,78.85 r270 bottom value=25.5k
R105 "CRCW0603150KJNEA" 0603_HV#1 126.525,50.075 r270 bottom value=150k
R106 "RC0603FR-071RL" 0603_HV#1 114.2,41.7 r180 bottom value=1.00
R107 "RC0603FR-0721K5L" 0603_HV#1 119.849,88.562 r0 bottom value=21.5k
R108 "B57371V2474J060" FP-B57371V2474J060_0603-MFG 101.2,45.025 r0 bottom value=470k
R109 "ERJ-6GEYJ335V" 0805_HV 98.45,38.25 r90 bottom value=3.3Meg
R110 "RC0603FR-0735K7L" 0603_HV#1 97.392,46.391 r270 bottom value=35.7k
R111 "RC0603FR-0714KL" 0603_HV#1 105.75,58.025 r0 bottom value=14.0k
R112 "RC0603JR-0710KL" 0603_HV#1 103.678,58.775 r90 bottom value=10k
R113 "CRCW0603200RFKEA" 0603_HV#1 113.25,50 r90 bottom value=200
R114 "ERJ-6GEYJ335V" 0805_HV 100.625,40.611 r270 bottom value=3.3Meg
R115 "ERJ-6GEYJ335V" 0805_HV 98.425,42.975 r270 bottom value=3.3Meg
R116 "CRCW0603750RFKEA" 0603_HV#1 98.85,73.8 r0 bottom value=750
R117 "RC0603FR-07100KL" 0603_HV#1 98.125,76 r90 bottom value=100k
R118 "M55342K12B10E0T" 0603_HV#1 101.05,76 r90 bottom value=10.0k
R119 "ERJ-3EKF4993V" 0603_HV#1 104.8,53.3 r180 bottom value=499k
R120 "CRCW0603825KFKEA" 0603_HV#1 101.886,50.229 r0 bottom value=825k
R121 "RC0603FR-07120KL" 0603_HV#1 106.94,52.586 r90 bottom value=120k
R122 "CSNL1206FT3L00" 1206 132.739,89.299 r0 bottom value=0.003
R123 "CRCW06034R70JNEA" 0603_HV#1 138.425,51.8 r270 bottom value=4.7
R125 "RC0603FR-07221KL" 0603#2 108.55,81.75 r90 bottom value=221k
R126 "CRCW06032K00JNEA" 0603_HV#1 104.925,73.85 r180 bottom value=2.0k
R127 "RC0603FR-071K47L" 0603_HV#1 107.848,79.056 r0 bottom value=1.47k
R128 "ERJ-6GEYJ120V" 0805_HV 133.14,73.301 r180 bottom value=12
R129 "ERJ-6GEYJ120V" 0805_HV 119.651,69.775 r180 bottom value=12
R130 "RC0603JR-07330RL" 0603_HV#3 123.8,85.4 r180 bottom value=330
R131 "RC0603JR-07330RL" 0603_HV#1 118.839,78.261 r0 bottom value=330
R132 "CRCW0603210KFKEA" 0603_HV#3 101.9,51.85 r180 bottom value=210k
RV1 "V275LA2P" Littelfuse_V275LA_7MM 43.7,83.75 r180 top
T1 "G244036LF" FP-G244036LF_PTH_XFRMR_29MM0_20MM6-MFG 125.4,66.475 r0 top locked
TP1 "N" Keystone5011 36.95,78.487 r0 top
TP2 "L" Keystone5011 37.175,88.875 r0 top locked
TP101 "OUT" Keystone5011 137.887,83.955 r0 top
TP106 "RTN" Keystone5011 138.065,89.2 r0 top
U1 "OPA2170AIDCUR" DCU0008A_N 106.959,76.67 r0 bottom
U2 "LM4040D25QDBZR" DBZ0003A_N 105.375,81.825 r180 bottom
U21 "LMG3622REQ" REQ0038A-MFG 75.025,37.375 r270 bottom locked
U22 "LMG3622REQ" REQ0038A-MFG 84.975,37.348 r270 bottom locked
U23 "UCC28056ADBVR" DBV0006A_N 78.527,24.618 r90 bottom
U101 "LMG3622REQ" REQ0038A-MFG 118.65,34.175 r90 bottom
U102 "UCC256604DDBR" DDB0014A-MFG 106.7,45.784 r0 bottom
U103 "LMG3622REQ" REQ0038A-MFG 120.675,45.2 r90 bottom
U105 "MP6924AGS-P" FP-MP6924AGS-P_SOIC8-MFG 119.825,82.85 r270 bottom locked

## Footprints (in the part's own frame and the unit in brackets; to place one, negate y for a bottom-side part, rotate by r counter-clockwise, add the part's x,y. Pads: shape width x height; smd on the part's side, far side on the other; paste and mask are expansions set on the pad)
0603#1 [mm] "0603 from SM-752 data"
  rect 1x0.95 smd: 1(-0.8,0) 2(0.8,0)
  silkscreen extent -1.52,-0.69 1.52,0.69, body extent -0.87,-0.47 0.87,0.47, height 1
0603#2 [mm] "0603 from SM-752 data"
  rect 0.8x0.95 smd: 1(-0.8,0) 2(0.8,0)
  silkscreen extent -1.52,-0.69 1.52,0.69, body extent -0.87,-0.47 0.87,0.47, height 1
0603_HV#1 [mil] "Ernesto recommended land pattern.  26 mil between pads."
  rect 30x30 smd: 1(-28,0) 2(28,0)
  silkscreen extent -52,-24 52,24, body extent -34,-19 34,19, height 39
0603_HV#2 [mil] "Ernesto recommended land pattern.  26 mil between pads."
  rect 27.56x30 smd: 1(-28,0) 2(28,0)
  silkscreen extent -52,-24 52,24, body extent -34,-19 34,19, height 39
0603_HV#3 [mil] "Ernesto recommended land pattern.  26 mil between pads."
  rect 26.77x30 smd: 1(-28,0) 2(28,0)
  silkscreen extent -52,-24 52,24, body extent -34,-19 34,19, height 39
0805_HV [mil] "0805 with 30mil clearance between pads"
  rect 50x63 smd: 1(-40,0) 2(40,0)
  silkscreen extent -74,-40 74,40, body extent -43,-29 43,29, height 57
1206 [mm] "1206 from SM-752 data"
  rect 1.3x1.85 smd: 1(-1.45,0) 2(1.45,0)
  silkscreen extent -2.4,-1.21 2.4,1.21, body extent -1.7,-0.9 1.7,0.9, height 1.35
1206_180 [mm] "1206_180"
  rect 1.1x1.6 smd: 1(-1.7,0) 2(1.7,0)
  silkscreen extent -0.9,-1 0.9,1, body extent -1.75,-0.95 1.75,0.95, height 1.8
1206_180M [mm] "1206_180"
  rect 1.5x1.95 smd: 1(-1.55,0) 2(1.55,0)
  silkscreen extent -2.76,-1.44 2.76,1.44, body extent -1.75,-0.95 1.75,0.95, height 1.8
1206_190 [mm] "1206_190"
  rect 1.1x1.6 smd: 1(-1.7,0) 2(1.7,0)
  silkscreen extent -0.9,-1 0.9,1, body extent -1.75,-0.95 1.75,0.95, height 1.9
1206L [mm] "1206 from SM-752 data"
  rect 1.1x1.75 smd: 1(-1.35,0) 2(1.35,0)
  silkscreen extent -0.4,-0.77 0.4,0.77, body extent -1.7,-0.9 1.7,0.9, height 1.35
C_film_17.5x7 [mm] "Xcap_Film 17.5 x 7mm"
  round 2.2 hole 1.3: 1(-7.5,0) 2(7.5,0)
  silkscreen extent -8.75,-3.5 8.75,3.5
Cap_12.5x40_H1 [mm]
  rrect50% 2x2 hole 1: 1(0,2.5)
  round 2 hole 1: 2(0,-2.5)
  silkscreen extent 2,-6.5 44,6.5
CE_Mark_5mm [mm] "Minimum text height for CE Mark"
  silkscreen extent -3.5,-2.5 3.5,2.5
CM_DCN181713H [mm]
  round 2 hole 1: 1(-5,7.5) 2(5,7.5) 3(5,-7.5) 4(-5,-7.5)
  silkscreen extent -8.75,-9 8.75,9
DBV0006A_N [mm] "SOT23, 6-Leads, Body 2.9x1.6mm, Pitch 0.95mm, Lead Span 2.8mm, IPC Medium Density"
  rrect17% 1x0.6 smd: 1(-1.375,0.95) 2(-1.375,0) 3(-1.375,-0.95) 4(1.375,-0.95) 5(1.375,0) 6(1.375,0.95)
  silkscreen extent -1.68,-1.55 0.5,1.55, body extent -1.42,-1.46 1.42,1.46, height 1.12
DBZ0003A_N [mm] "SOT23, 3-Leads, Body 2.9x1.3mm, Pitch 0.95mm, Lead Span 2.4mm, IPC Medium Density"
  rrect17% 1x0.6 smd: 1(-1.2,0.95) 2(-1.2,-0.95) 3(1.2,0)
  silkscreen extent 0.2,-1.5 0.7,1.5, body extent -1.26,-1.46 1.26,1.46, height 0.98
DCU0008A_N [mm] "TSSOP, 8-Leads, Body 2x2.3mm, Pitch 0.5mm, IPC Medium Density"
  oval 0.8x0.3 smd: 1(-1.6,0.75) 2(-1.6,0.25) 3(-1.6,-0.25) 4(-1.6,-0.75) 5(1.6,-0.75) 6(1.6,-0.25) 7(1.6,0.25) 8(1.6,0.75)
  silkscreen extent -1.05,-1.05 0.38,1.05, body extent -1.56,-1 1.56,1, height 0.9
DDB0014A-MFG [mm]
  rrect17% 1.55x0.6 smd paste+0 mask+0: 1(-2.7,4.445) 3(-2.7,1.905) 4(-2.7,0.635) 5(-2.7,-0.635) 6(-2.7,-1.905) 7(-2.7,-3.175) 8(-2.7,-4.445) 9(2.7,-4.445) 10(2.7,-3.175) 11(2.7,-1.905) 12(2.7,-0.635) 14(2.7,1.905) 15(2.7,3.175) 16(2.7,4.445)
  silkscreen extent -4.12,-5 2,5, body extent -3.01,-4.95 3.01,4.95, height 1.75
DK1_86 [mm] "SMD, 2-Leads, Body 8x6mm"
  rrect5% 2.2x3.6 smd: 1(-5.1,0) 2(5.1,0)
  silkscreen extent -4.3,-3.3 4.3,3.3, body extent -5.95,-3.25 5.95,3.25, height 2.5
DNK0008A [mm] "SON, 8-Leads, Body 5x6mm"
  rrect39% 0.86x0.51 smd paste-0.05 mask-0.05: 1(-2.82,1.905) 2(-2.82,0.635) 3(-2.82,-0.635) 4(-2.82,-1.905) 5(2.82,-1.905) 6(2.82,-0.635) 7(2.82,0.635) 8(2.82,1.905)
  rrect8% 1.48x1.27 on Bottom Paste: 9(-0.18,-1.47) 9(-0.18,0) 9(-0.18,1.47) 9(1.5,-1.47) 9(1.5,0) 9(1.5,1.47)
  rrect5% 4.34x4.6 smd paste-3 mask-0.05: 9(1.08,0)
  silkscreen extent -3.2,-2.7 3.2,2.7, body extent -3.05,-2.55 3.05,2.55, height 1.06
FCC_disclaimer [mm]
FP-227AVG035MFBJ_RADIAL-MFG [mm]
  round 1.25 hole 0.75 paste-1000 mask+0: 1(-1.75,0)
  rrect50% 1.25x1.25 hole 0.75 paste-1000 mask+0: 2(1.75,0)
  silkscreen extent -4.25,-4.25 4.25,4.25, body extent -4.35,-4.35 4.35,4.35, height 0.25
FP-202410103L250W_PTH3-MFG [mm] "Recommended Land Pattern"
  round 2 hole 1.1 paste-2539.97 mask+0: 2(-6.75,-21.75) 3(-2.25,-21.75) 4(2.25,-21.75)
  silkscreen extent -16.75,-16.75 16.75,16.75, body extent -16.85,-22.57 16.85,16.85, height 0.25
FP-B57371V2474J060_0603-MFG [mm]
  rrect10% 1x1 smd paste+0 mask+0: 1(-1,0) 2(1,0)
  silkscreen extent -0.13,-0.47 0.13,0.47, body extent -0.8,-0.4 0.8,0.4, height 0.9
FP-G244036LF_PTH_XFRMR_29MM0_20MM6-MFG [mm]
  round 2.2 hole 1.4 paste-2539.97 mask+0: 1(2.575,-22.175)
  round 1.5 hole 0.8 paste-2539.97 mask+0: 3(12.709,-17.15) 4(9.125,-17.175)
  round 2 hole 1.05 paste-2539.97 mask+0: 5(-7,9.6)
  round 2 hole 1.2 paste-2539.97 mask+0: 6(-3.5,9.6) 8(3.5,9.6) 9(7,9.6)
  silkscreen extent -14.5,-10.3 14.5,10.3, body extent -14.6,-19.45 14.6,10.5, height 0.25
FP-G244038LF_PTH2-MFG [mm]
  rrect8% 2x2 hole 1 paste-2539.97 mask+0: 1(-4.005,-5.15)
  oval 2x1.6 hole 1 paste-2539.97 mask+0: 4(4.005,-5.15)
  silkscreen extent -8.95,-7.7 8.95,7, body extent -9.05,-7.1 9.05,7.1, height 0.25
FP-MP6924AGS-P_SOIC8-MFG [mm]
  rrect16% 1.6x0.61 smd paste+0 mask+0: 1(-2.7,1.905) 2(-2.7,0.635) 3(-2.7,-0.635) 4(-2.7,-1.905) 5(2.7,-1.905) 6(2.7,-0.635) 7(2.7,0.635) 8(2.7,1.905)
  silkscreen extent -4.17,-2.5 1.5,2.5, body extent -3,-2.45 3,2.45, height 1.75
FP-R413D1100JMT0K_RADIAL-MFG [mm]
  rrect8% 2x2 hole 1 paste-1000 mask+0: 1(-3.75,0)
  round 2 hole 1 paste-1000 mask+0: 2(3.75,0)
  silkscreen extent -5.1,-2.05 5.1,2.05, body extent -5.2,-2.15 5.2,2.15, height 0.25
FP-TLP383(GR-TPL,E_SO6-4-MFG [mm]
  rrect13% 1.3x0.8 smd paste+0 mask+0: 1(-4.75,1.27) 3(-4.75,-1.27) 4(4.75,-1.27) 6(4.75,1.27)
  silkscreen extent -3.7,-2.02 3.7,2.02, body extent -5.01,-1.92 5.01,1.92, height 2.3
FUSE_392 [mm] "LITTELFUSE"
  round 1.7 hole 1.1: 1(-2.54,0) 2(2.54,0)
  silkscreen extent -4.32,-2.03 4.32,2.03, body extent -4.25,-2 4.25,2, height 8
GBL610 [mm]
  oval 2.4x1.6 / inner oval 2.4x1.2 / far side oval 2.5x1.7 hole 0.9 slot 1.8 at 0 deg mask+0.03: 1(-7.5,-2.4) 2(-2.5,-2.4) 3(2.5,-2.4) 4(7.5,-2.4)
  silkscreen extent -10.3,-3.55 10.3,-0.05, body extent -10.3,-3.6 10.3,-0.1, height 13.5
Keystone5011 [mil] "Keystone Multipurpose loops"
  round 87 hole 63: 1(0,0)
  silkscreen extent -70,-70 70,70, body extent -63,-63 63,62, height 319
L_Ring_H_D=16.76mm [mm]
  round 2 hole 1.1: 1(-6.975,0) 2(6.975,0)
  silkscreen extent -8.38,-8.38 8.38,8.38
Littelfuse_V275LA_7MM [mm] "TH, 2-Leads, Dia 9mm"
  round 2 hole 1: 1(-2.5,-1.25) 2(2.5,1.25)
  silkscreen extent -4.5,-2.8 4.5,2.8, body extent -4.5,-2.8 4.49,2.8, height 10.5
PHE426_1300x400x900#1 [mm] "TH, 2-Leads, Body 13x4mm, Lead Spacing 10mm"
  round 2 hole 1: 1(-5,0) 2(5,0)
  silkscreen extent -6.5,-2 6.5,2, body extent -6.5,-2 6.5,2, height 9
PHE426_1300x400x900#2 [mm] "TH, 2-Leads, Body 13x4mm, Lead Spacing 10mm"
  oval 1.6x2.4 hole 1: 1(-5,0)
  oval 2x1.6 hole 1: 2(5,0)
  silkscreen extent -6.5,-2 6.5,2, body extent -6.5,-2 6.5,2, height 9
REQ0038A-MFG [mm]
  rrect20% 0.7x0.5 smd paste-1000 mask+0: 1(-2.5,3.625) 15(-2.5,-3.625) 20(2.5,-3.625) 34(2.5,3.625)
  rrect40% 0.7x0.25 smd paste+0 mask+0: 2(-2.5,3) 3(-2.5,2.5) 4(-2.5,2) 5(-2.5,1.5) 6(-2.5,1) 7(-2.5,0.5) 8(-2.5,0) 9(-2.5,-0.5) 10(-2.5,-1) 11(-2.5,-1.5) 12(-2.5,-2) 13(-2.5,-2.5) 14(-2.5,-3) 21(2.5,-3) 22(2.5,-2.5) 23(2.5,-2) 24(2.5,-1.5) 25(2.5,-1) 26(2.5,-0.5) 27(2.5,0) 28(2.5,0.5) 29(2.5,1) 30(2.5,1.5) 31(2.5,2) 32(2.5,2.5) 33(2.5,3)
  rrect40% 0.25x0.7 smd paste+0 mask+0: 16(0.275,-3.85) 17(0.775,-3.85) 18(1.275,-3.85) 19(1.775,-3.85) 35(1.775,3.85) 36(1.275,3.85) 37(0.775,3.85) 38(0.275,3.85)
  rrect5% 2.1x6.6 smd paste-1000 mask+0: 39(0.9,0)
  silkscreen extent -3.62,-4.05 -0.23,4.05, body extent -2.65,-4 2.65,4, height 1
Rubycon_630x1100 [mm] "TH, 2-Leads, Dia 6.3mm, Lead Spacing 2.5mm"
  rrect50% 1.5x1.5 hole 0.8: 1(-1.25,0)
  round 1.5 hole 0.8: 2(1.25,0)
  silkscreen extent -3.4,-3.4 3.41,3.4, body extent -3.4,-3.4 3.41,3.4, height 12.51
SMB [mm] "Molded Diode, 2-Leads, Body 5.4x3.6mm, IPC Medium Density, based on OnSemi component dimensions"
  rect 2.159x2.743 smd: 1(-2.21,0) 2(2.21,0)
  silkscreen extent -3.94,-2.08 3.18,2.08, body extent -2.7,-1.8 2.7,1.8, height 2.32
SOD-123 [mm] "On Semi recommended land pattern"
  rect 0.915x1.22 smd: 1(-1.638,0) 2(1.638,0)
  silkscreen extent -2.74,-1.17 2.03,1.17, body extent -1.93,-0.9 1.93,0.9, height 1.35
SOD-123FL [mm] "Copied from SOD-123"
  rect 0.915x1.22 smd: 1(-1.637,0) 2(1.637,0)
  silkscreen extent -2.74,-1.16 1.68,1.16, body extent -1.9,-0.9 1.9,0.9, height 1
SOD-323 [mm] "NXP recommended land pattern"
  rect 0.6x0.6 smd paste-0.05: 1(-1.1,0) 2(1.1,0)
  silkscreen extent -2.06,-0.86 1.53,0.86, body extent -1.3,-0.67 1.3,0.68, height 1.1
SOT-23 [mm] "SOT23, 3-Leads, Body 2.9x1.3mm, Pitch 0.95mm, Lead Span 2.5mm, IPC Medium Density"
  rrect50% 1x0.6 smd: 1(-1.2,0.95) 2(-1.2,-0.95) 3(1.2,0)
  silkscreen extent -1.62,-1.5 0.7,1.5, body extent -1.16,-1.45 1.21,1.45, height 1
SOT-363 [mm]
  rect 0.6x0.42 smd mask+0.051: 1(-0.95,0.65) 2(-0.95,0) 3(-0.95,-0.65) 4(0.95,-0.65) 5(0.95,0) 6(0.95,0.65)
  silkscreen extent -0.38,-1.02 0.38,1.02, body extent -1.1,-1.1 1.1,1.1, height 1.12
TI_Stacked_Overlay_Small [mm]
  silkscreen extent -10.63,-2.49 10.63,2.49
TO-220AB [mm] "Copied from Altium's version of TO3B"
  rrect25% 1.8x3 hole 1.27: 1(-2.54,0)
  oval 1.8x3 hole 1.27: 2(0,0) 3(2.54,0)
  silkscreen extent -5.61,-1.49 5.61,3.2, body extent -5.61,-1.49 5.61,3.2, height 19.42
WCAP-FTX2_1500x700x1250 [mm] "TH, 2-Leads, Body 15x7mm, Pin Spacing 12.5mm"
  round 2 hole 1.1: 1(-6.25,0) 2(6.25,0)
  silkscreen extent -7.5,-3.6 7.5,3.6, body extent -7.5,-3.5 7.5,3.5, height 12.3
WE-CMB_NiZn_S [mm] "TH, 4-Leads, Body 18.5x14.5mm"
  rect 2x2 hole 1.3: 1(-2.5,3.85)
  round 2 hole 1.3: 2(2.5,3.85) 3(2.5,-3.85) 4(-2.5,-3.85)
  silkscreen extent -6.5,-8.1 6.5,8.37, body extent -6.53,-8.09 6.52,8.09, height 19.55
WEEE_Minimum [mm] "WEEElie bin"
  silkscreen extent -2.42,-4.38 2.52,2.65

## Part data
BD1 BD2: library part BD
C1: library part CMP-0047964-1, "1000 pF Film Capacitor 300V 1500V (1.5kV) Polypropylene (PP), Metallized Radial", Digikey Part Number=399-R413D1100JMT0K-ND, Manufacturer=KEMET, Mouser Part Number=80-R413D1100JMT0K, Operating Temperature Range="-40°C to +125°C", Tolerance_%=10%, ValueDisplayed=1000pF, Voltage Ac Rating Y=300V
C2: library part CMP-0012312-3, "CAP, Film, 0.22 uF, 275 V, +/- 10%, TH", Cap_Case=15x7x12.5, Manufacturer="Wurth Elektronik", Supplier Part Number 1=732-5888-ND, Tolerance_%=10%, Value1=Unknown, Value2=275V, ValueDisplayed=0.22uF
C3 C104 C105: library part CMP-0121632-1, "220 µF 35 V Aluminum - Polymer Capacitors Radial, Can 26mOhm 1500 Hrs @ 125°C", Digikey Part Number=1572-1695-ND, Leakage Current=1540uA, Manufacturer="Cornell Dubilier", Mouser Part Number=598-227AVG035MFBJ, Operating Temperature Range="-55°C to +125°C", Tolerance_%=20%, ValueDisplayed=220uF
C4: library part CMP-0080807-1, "CAP, AL, 100 µF, 35 V, +/- 20%, TH", Cap_Case=6.3x11, Manufacturer=Rubycon, Supplier Part Number 1=1189-2268-ND, Tolerance_%=20%, Value2=35V, ValueDisplayed=100µF
C5: library part CMP-0006921-2, "CAP, CERM, 330 pF, 50 V, +/- 10%, X7R, 0603", Cap_Case=0603, Manufacturer=Kemet, Supplier Part Number 1=399-1073-1-ND, TempCo=X7R, Tolerance_%=10%, Value1=Unknown, Value2=50V, ValueDisplayed=330pF
C6: library part CMP-0860569-1, "CAP, CERM, 10 µF, 25 V,+/- 10%, X5R, 0603", Cap_Case=0603, Manufacturer=MuRata, TempCo=X5R, Tolerance_%=10%, Value2=25V, ValueDisplayed=10µF
C7: library part CMP-0006854-1, "CAP, CERM, 0.01 uF, 50 V, +/- 10%, X7R, 0603", Cap_Case=0603, Manufacturer=Kemet, Supplier Part Number 1=399-1091-1-ND, TempCo=X7R, Tolerance_%=10%, Value1=Unknown, Value2=50V, ValueDisplayed=0.01uF
C8: library part CMP-0006790-2, "CAP, CERM, 470 pF, 50 V, +/- 5%, C0G/NP0, 0603", Cap_Case=0603, Manufacturer=AVX, Supplier Part Number 1=478-1183-1-ND, TempCo=C0G/NP0, Tolerance_%=5%, Value1="0.063 ohm", Value2=50V, ValueDisplayed=470pF
C9: library part CMP-0007144-2, "CAP, CERM, 0.1 uF, 50 V, +/- 10%, X7R, 0603", Cap_Case=0603, Manufacturer=MuRata, Supplier Part Number 1=490-4779-1-ND, TempCo=X7R, Tolerance_%=10%, Value1="0.02 ohm", Value2=50V, ValueDisplayed=0.1uF
C10 C101 C110: library part CMP-0079095-1, "CAP, CERM, 0.1 µF, 50 V,+/- 10%, X7R, AEC-Q200 Grade 1, 0603", Cap_Case=0603, Manufacturer=AVX, Supplier Part Number 1=478-3540-1-ND, TempCo=X7R, Tolerance_%=10%, Value2=50V, ValueDisplayed=0.1µF
C21 C23 C117 C128: library part CMP-0079720-1, "CAP, CERM, 1 µF, 25 V,+/- 10%, X7R, 0603", Cap_Case=0603, Manufacturer=MuRata, Supplier Part Number 1=490-10888-1-ND, TempCo=X7R, Tolerance_%=10%, Value2=25V, ValueDisplayed=1µF
C22 C24 C102 C111: library part CMP-0007071-4, "CAP, CERM, 22 pF, 50 V, +/- 5%, C0G/NP0, AEC-Q200 Grade 1, 0603", Cap_Case=0603, Manufacturer=TDK, Supplier Part Number 1=445-5632-1-ND, TempCo=C0G/NP0, Tolerance_%=5%, Value1=Unknown, Value2=50V, ValueDisplayed=22pF
C25 C27: library part C_film, Alternate Manufacturer=-, Manufacturer="Used in BOM report"
C28: library part CMP-0009029-2, "CAP, CERM, 10 pF, 1000 V, +/- 5%, C0G/NP0, 1206", Cap_Case=1206, Manufacturer=Vishay-Vitramon, Supplier Part Number 1=720-1010-1-ND, TempCo=C0G/NP0, Tolerance_%=5%, Value1=Unknown, Value2=1000V, ValueDisplayed=10pF
C29 C30: library part E-Cap, "EKXN451ELL820MK40S", Alternate Manufacturer=-, Manufacturer="Used in BOM report"
C31: library part CMP-0008728-1, "CAP, CERM, 0.1 uF, 450 V, +/- 10%, X7T, 1206", Cap_Case=1206, Manufacturer=TDK, Supplier Part Number 1=445-8897-1-ND, TempCo=X7T, Tolerance_%=10%, Value1=Unknown, Value2=450V, ValueDisplayed=0.1uF
C32: library part CMP-0007210-1, "CAP, CERM, 3300 pF, 50 V, +/- 5%, C0G/NP0, 0603", Cap_Case=0603, Manufacturer=MuRata, Supplier Part Number 1=GRM1885C1H332JA01D-ND, TempCo=C0G/NP0, Tolerance_%=5%, Value1=Unknown, Value2=50V, ValueDisplayed=3300pF
C33: library part CMP-0007197-4, "CAP, CERM, 220 pF, 50 V, +/- 5%, C0G/NP0, 0603", Cap_Case=0603, Manufacturer=MuRata, Supplier Part Number 1=490-1435-1-ND, TempCo=C0G/NP0, Tolerance_%=5%, Value1=Unknown, Value2=50V, ValueDisplayed=220pF
C36: library part CMP-0007145-3, "CAP, CERM, 0.22 uF, 50 V, +/- 10%, X7R, AEC-Q200 Grade 1, 0603", Cap_Case=0603, Manufacturer=MuRata, Supplier Part Number 1=490-5402-1-ND, TempCo=X7R, Tolerance_%=10%, Value1=Unknown, Value2=50V, ValueDisplayed=0.22uF
C37 C39: library part CMP-0006754-4, "CAP, CERM, 1 uF, 25 V, +/- 10%, X7R, 0603", Cap_Case=0603, Manufacturer=AVX, Supplier Part Number 1=478-10046-1-ND, TempCo=X7R, Tolerance_%=10%, Value1=Unknown, Value2=25V, ValueDisplayed=1uF
C38: library part CMP-0007451-3, "CAP, CERM, 0.033 uF, 50 V, +/- 10%, X7R, 0603", Cap_Case=0603, Manufacturer=MuRata, Supplier Part Number 1=490-3286-1-ND, TempCo=X7R, Tolerance_%=10%, Value1=Unknown, Value2=50V, ValueDisplayed=0.033uF
C40: library part CMP-0006932-4, "CAP, CERM, 390 pF, 50 V, +/- 5%, C0G/NP0, 0603", Cap_Case=0603, Manufacturer=Kemet, Supplier Part Number 1=399-1069-1-ND, TempCo=C0G/NP0, Tolerance_%=5%, Value1=Unknown, Value2=50V, ValueDisplayed=390pF
C41: library part CMP-0006898-4, "CAP, CERM, 2200 pF, 50 V, +/- 10%, X7R, 0603", Cap_Case=0603, Manufacturer=Kemet, Supplier Part Number 1=399-1085-1-ND, TempCo=X7R, Tolerance_%=10%, Value1=Unknown, Value2=50V, ValueDisplayed=2200pF
C103 C109: library part CMP-0012541-3, "CAP, Film, 0.015 uF, 630 V, +/- 20%, TH", Cap_Case=13x4x9mm, Manufacturer=Kemet, Supplier Part Number 1=399-11726-ND, Tolerance_%=20%, Value1=Unknown, Value2=630V, ValueDisplayed=0.015uF
C106 C107: library part CMP-0008802-1, "CAP, CERM, 10 uF, 50 V, +/- 10%, X7R, 1206", Cap_Case=1206, Manufacturer=Samsung, Supplier Part Number 1=1276-6767-1-ND, TempCo=X7R, Tolerance_%=10%, Value1=Unknown, Value2=50V, ValueDisplayed=10uF
C108: library part CMP-0008885-2, "CAP, CERM, 150 pF, 630 V, +/- 5%, C0G/NP0, 1206", Cap_Case=1206, Manufacturer=MuRata, Supplier Part Number 1=490-5274-1-ND, TempCo=C0G/NP0, Tolerance_%=5%, Value1=Unknown, Value2=630V, ValueDisplayed=150pF
C112 C112A: library part CMP-0007843-1, "CAP, CERM, 15 uF, 35 V, +/- 20%, X5R, 0805", Cap_Case=0805, Manufacturer=TDK, Supplier Part Number 1=445-14423-1-ND, TempCo=X5R, Tolerance_%=20%, Value1="0.001669 ohm", Value2=35V, ValueDisplayed=15uF
C113: library part CMP-0006943-4, "CAP, CERM, 4700 pF, 50 V, +/- 10%, X7R, 0603", Cap_Case=0603, Manufacturer=Kemet, Supplier Part Number 1=399-1087-1-ND, TempCo=X7R, Tolerance_%=10%, Value1=Unknown, Value2=50V, ValueDisplayed=4700pF
C114: library part CMP-0007498-4, "CAP, CERM, 4.7 uF, 10 V, +/- 20%, X7R, 0603", Cap_Case=0603, Manufacturer=MuRata, TempCo=X7R, Tolerance_%=20%, Value1=Unknown, Value2=10V, ValueDisplayed=4.7uF
C115: library part CMP-0007052-4, "CAP, CERM, 1 uF, 35 V, +/- 10%, X7R, 0603", Cap_Case=0603, Manufacturer=TDK, Supplier Part Number 1=445-7414-1-ND, TempCo=X7R, Tolerance_%=10%, Value1=Unknown, Value2=35V, ValueDisplayed=1uF
C116: library part CMP-0007437-3, "CAP, CERM, 1500 pF, 50 V, +/- 10%, X7R, 0603", Cap_Case=0603, Manufacturer=MuRata, Supplier Part Number 1=490-1498-1-ND, TempCo=X7R, Tolerance_%=10%, Value1=Unknown, Value2=50V, ValueDisplayed=1500pF
C118: library part CMP-0006770-4, "CAP, CERM, 180 pF, 50 V, +/- 5%, C0G/NP0, 0603", Cap_Case=0603, Manufacturer=AVX, Supplier Part Number 1=478-1178-1-ND, TempCo=C0G/NP0, Tolerance_%=5%, Value1="0.09 ohm", Value2=50V, ValueDisplayed=180pF
C119: library part CMP-0007049-4, "CAP, CERM, 0.047 uF, 50 V, +/- 10%, X7R, 0603", Cap_Case=0603, Manufacturer=TDK, Supplier Part Number 1=445-1313-1-ND, TempCo=X7R, Tolerance_%=10%, Value1="0.049007 ohm", Value2=50V, ValueDisplayed=0.047uF
C120: library part CMP-0007197-1, "CAP, CERM, 220 pF, 50 V, +/- 5%, C0G/NP0, 0603", Cap_Case=0603, Manufacturer=MuRata, Supplier Part Number 1=490-1435-1-ND, TempCo=C0G/NP0, Tolerance_%=5%, Value1=Unknown, Value2=50V, ValueDisplayed=220pF
C121: library part CMP-0080091-1, "CAP, CERM, 100 pF, 50 V,+/- 1%, C0G/NP0, 0603", Cap_Case=0603, Manufacturer=Kemet, Supplier Part Number 1=399-7819-1-ND, TempCo=C0G/NP0, Tolerance_%=1%, Value2=50V, ValueDisplayed=100pF
C122 C123: library part CMP-0084048-1, "CAP, CERM, 0.022 µF, 1000 V,+/- 10%, X7R, AEC-Q200 Grade 1, 1206", Cap_Case=1206, Manufacturer=Kemet, TempCo=X7R, Tolerance_%=10%, Value2=1000V, ValueDisplayed=0.022µF
C124: library part CMP-0006861-4, "CAP, CERM, 0.1 uF, 50 V, +/- 10%, X7R, 0603", Cap_Case=0603, Manufacturer=Kemet, Supplier Part Number 1=399-5089-1-ND, TempCo=X7R, Tolerance_%=10%, Value1=Unknown, Value2=50V, ValueDisplayed=0.1uF
C125 C126: library part CMP-0006992-4, "CAP, CERM, 100 pF, 100 V, +/- 1%, C0G/NP0, 0603", Cap_Case=0603, Manufacturer=TDK, Supplier Part Number 1=445-5378-1-ND, TempCo=C0G/NP0, Tolerance_%=1%, Value1=Unknown, Value2=100V, ValueDisplayed=100pF
C127: library part CMP-0006976-5, "CAP, CERM, 1000 pF, 50 V, +/- 10%, X7R, 0603", Cap_Case=0603, Manufacturer=Kemet, Supplier Part Number 1=399-5348-1-ND, TempCo=X7R, Tolerance_%=10%, Value1=Unknown, Value2=50V, ValueDisplayed=1000pF
CY1 CY2 CY101: library part CMP-0077997-1, "CAP, CERM, 1000 pF, X1 440 VAC/Y1 250 VAC, +/- 20%, E, 8x6mm", Cap_Case=8x6mm, Manufacturer=MuRata, TempCo=E, Tolerance_%=20%, ValueDisplayed=1000pF
D1 D5: library part CMP-0076928-2, "Diode, Schottky, 40 V, 0.35 A, SOD-323", Manufacturer="Micro Commercial Components", Value1=0.35A, Value2=0.6V
D2 D3: library part CMP-0029032-2, "Diode, GP, 1KV, 1 A, SOD-123F", Manufacturer="ON Semiconductor", Supplier Part Number 1=ES1JFLDKR-ND, Value1=1A, Value2=1V
D4: library part CMP-0005835-4, "Diode, Zener, 18 V, 200 mW, SOD-323", Manufacturer="Diodes Inc.", Power_W=200mW, Value1=0.2W
D21 D25: library part CMP-0077014-1, "Diode, GP, 1000V, 3 A, SMB", Manufacturer="Diodes Incorporated", Supplier Part Number 1=497-3771-1-ND, Value1=3A, Value2=1.3V
D22: library part CMP-0085337-1, "Diode, Ultrafast, 600 V, 8 A, TO-220AB", Manufacturer="ON Semiconductor", Value1=8A, Value2=16V
D23 D24 D101: library part CMP-0079597-2, "Diode, Switching, 75 V, 0.15 A, AEC-Q101, SOD-323", Manufacturer="Diodes Inc.", Value1=0.15A, Value2=1.25V
D102: library part CMP-0029148-2, "Diode, Ultrafast, 600 V, 1 A, SOD-123FL", Manufacturer="Micro Commercial Components", Value1=1A, Value2=1.7V
D103: library part CMP-0085773-1, "Diode, Zener, 27 V, 300 mW, SOD-323", Manufacturer="ON Semiconductor", Power_W=300mW, Value1=0.3W
F1: library part CMP-0003561-2, "Fuse, 3.15 A, 250VAC/VDC, TH", Irating_A=3.15A, Manufacturer=Littelfuse, Supplier Part Number 1=F5504CT-ND
L1: library part CMP-0013095-2, "Coupled inductor, 5 A, 0.013 ohm, TH", Manufacturer="Wurth Elektronik", Supplier Part Number 1=732-3246-ND
L2: library part CM_Choke_Planar, Alternate Manufacturer=-, Manufacturer="Used in BOM report"
L3: library part CMP-0123590-1, "RESONANT INDUCTOR", Manufacturer=GCI, Operating Temperature Range="0°C to +85°C", Test Frequency=100kHz, Tolerance_%=5%
L4: library part CMP-0124119-1, "250W  PFC Inductor", Manufacturer=3L, Operating Temperature Range=to, Part Number=202410103L250W, Test Frequency=10kHz, Tolerance_%=10%
L22: library part L_FIX, Alternate Manufacturer=-, Manufacturer="Used in BOM report"
Logo1: library part CMP-0074844-1
Logo2: library part CMP-0074838-1, "Texas Instrument Corporate Signature"
Logo3: library part CMP-0074847-1, "FCC_disclaimer"
Logo4: library part CMP-0074769-1
Q1: library part CMP-0000769-1, "MOSFET, N-CH, 60 V, 0.17 A, SOT-23", Alternate Manufacturer=None, Manufacturer="Diodes Inc.", Supplier Part Number 1=2N7002-FDICT-ND, Value1=7, Value2="223 nC"
Q2: library part CMP-0000615-1, "MOSFET, 2-CH, N-CH, 30 V, 0.22 A, AEC-Q101, SOT-363", Alternate Manufacturer=None, Manufacturer="Diodes Inc.", Supplier Part Number 1=DMN63D8LDW-7CT-ND, Value1=4, Value2="0.43 nC"
Q101 Q102: library part CMP-0000823-1, "MOSFET, N-CH, 60 V, 100 A, DNK0008A (VSON-CLIP-8)", Alternate Manufacturer=None, Manufacturer="Texas Instruments", Supplier Part Number 1=296-41076-1-ND, Value1=0.003, Value2="41 nC"
Q103 Q104: library part CMP-0087394-2, "Optoisolator Transistor Output 5000Vrms 1 Channel 6-SO", Manufacturer=Toshiba
R1 R2: library part CMP-0018641-3, "RES, 2.2 k, 5%, 0.25 W, AEC-Q200 Grade 0, 1206", Manufacturer=Vishay-Dale, Power_W=250mW, Supplier Part Number 1=541-2.2KECT-ND, TempCo="200 ppm/C", Tolerance_%=5%, Value2=0.25W, Value_Code=2k20, ValueDisplayed=2.2k
R3: library part CMP-0025885-5, "RES, 0, 5%, 0.1 W, 0603", Manufacturer=Yageo, Power_W=100mW, Supplier Part Number 1=311-0.0GRCT-ND, TempCo="200 ppm/C", Tolerance_%=5%, Value2=0.1W, Value_Code=0000, ValueDisplayed=0
R4: library part CMP-0082530-1, "RES, 100 k, 5%, 0.1 W, 0603", Manufacturer=Vishay-Dale, Power_W=100mW, Supplier Part Number 1=541-3992-1-ND, TempCo="200 ppm/C", Tolerance_%=5%, Value2=0.1W, Value_Code=100k
R5 R7: library part CMP-0081973-1, "RES, 0, 0%, 0.25 W, AEC-Q200 Grade 0, 0603", Manufacturer=Vishay-Dale, Power_W=250mW, Supplier Part Number 1=541-2779-1-ND, Tolerance_%=0%, Value2=0.25W, Value_Code=0
R6: library part CMP-0025822-1, "RES, 510 k, 5%, 0.1 W, 0603", Manufacturer=Vishay-Dale, Power_W=100mW, Supplier Part Number 1=541-510KGCT-ND, TempCo="200 ppm/C", Tolerance_%=5%, Value2=0.1W, Value_Code=510k
R8 R123: library part CMP-0025821-4, "RES, 4.7, 5%, 0.1 W, AEC-Q200 Grade 0, 0603", Manufacturer=Vishay-Dale, Power_W=100mW, Supplier Part Number 1=541-4.7GCT-ND, TempCo="200 ppm/C", Tolerance_%=5%, Value2=0.1W, Value_Code=4R70, ValueDisplayed=4.7
R9: library part CMP-0022204-4, "RES, 20.0 k, 1%, 0.1 W, AEC-Q200 Grade 0, 0603", Manufacturer=Vishay-Dale, Power_W=100mW, Supplier Part Number 1=541-20.0KHCT-ND, TempCo="100 ppm/C", Tolerance_%=1%, Value2=0.1W, Value_Code=20k0, ValueDisplayed=20.0k
R10: library part CMP-0025701-1, "RES, 10 k, 5%, 0.1 W, 0603", Manufacturer=Vishay-Dale, Power_W=100mW, Supplier Part Number 1=541-10KGCT-ND, TempCo="200 ppm/C", Tolerance_%=5%, Value2=0.1W, Value_Code=10k0, ValueDisplayed=10k
R21 R23 R28: library part CMP-0021137-3, "RES, 2.74 M, 1%, 0.125 W, AEC-Q200 Grade 0, 0805", Manufacturer=Vishay-Dale, Power_W=125mW, Supplier Part Number 1=541-2.74MCCT-ND, TempCo="100 ppm/C", Tolerance_%=1%, Value2=0.125W, Value_Code=2M74, ValueDisplayed=2.74M
R22 R26 R27: library part CMP-0021222-4, "RES, 3.24 M, 1%, 0.125 W, AEC-Q200 Grade 0, 0805", Manufacturer=Vishay-Dale, Power_W=125mW, Supplier Part Number 1=541-3.24MCCT-ND, TempCo="100 ppm/C", Tolerance_%=1%, Value2=0.125W, Value_Code=3M24, ValueDisplayed=3.24M
R24 R25 R101 R105: library part CMP-0025717-4, "RES, 150 k, 5%, 0.1 W, AEC-Q200 Grade 0, 0603", Manufacturer=Vishay-Dale, Power_W=100mW, Supplier Part Number 1=541-150KGCT-ND, TempCo="200 ppm/C", Tolerance_%=5%, Value2=0.1W, Value_Code=150k
R29: library part CMP-0022943-5, "RES, 24.3 k, 1%, 0.1 W, 0603", Manufacturer=Yageo, Power_W=100mW, Supplier Part Number 1=311-24.3KHRCT-ND, TempCo="100 ppm/C", Tolerance_%=1%, Value2=0.1W, Value_Code=24k3, ValueDisplayed=24.3k
R30: library part CMP-0021005-3, "RES, 1.82 M, 1%, 0.125 W, AEC-Q200 Grade 0, 0805", Manufacturer=Vishay-Dale, Power_W=125mW, Supplier Part Number 1=541-1.82MCCT-ND, TempCo="100 ppm/C", Tolerance_%=1%, Value2=0.125W, Value_Code=1M82, ValueDisplayed=1.82M
R31: library part CMP-0023229-5, "RES, 64.9, 1%, 0.1 W, 0603", Manufacturer=Yageo, Power_W=100mW, Supplier Part Number 1=311-64.9HRCT-ND, TempCo="100 ppm/C", Tolerance_%=1%, Value2=0.1W, Value_Code=64R9, ValueDisplayed=64.9
R32: library part CMP-0025754-1, "RES, 20, 5%, 0.1 W, 0603", Manufacturer=Vishay-Dale, Power_W=100mW, Supplier Part Number 1=541-20GCT-ND, TempCo="200 ppm/C", Tolerance_%=5%, Value2=0.1W, Value_Code=20R0, ValueDisplayed=20
R33: library part CMP-0025939-5, "RES, 750, 5%, 0.1 W, 0603", Manufacturer=Yageo, Power_W=100mW, Supplier Part Number 1=311-750GRCT-ND, TempCo="100 ppm/C", Tolerance_%=5%, Value2=0.1W, Value_Code=750R, ValueDisplayed=750
R34 R38: library part CMP-0025815-4, "RES, 47, 5%, 0.1 W, AEC-Q200 Grade 0, 0603", Manufacturer=Vishay-Dale, Power_W=100mW, Supplier Part Number 1=541-47GCT-ND, TempCo="200 ppm/C", Tolerance_%=5%, Value2=0.1W, Value_Code=47R0, ValueDisplayed=47
R35: library part CMP-0025725-2, "RES, 180 k, 5%, 0.1 W, 0603", Manufacturer=Vishay-Dale, Power_W=100mW, Supplier Part Number 1=541-180KGCT-ND, TempCo="200 ppm/C", Tolerance_%=5%, Value2=0.1W, Value_Code=180k
R36: library part CMP-0025755-4, "RES, 220 k, 5%, 0.1 W, AEC-Q200 Grade 0, 0603", Manufacturer=Vishay-Dale, Power_W=100mW, Supplier Part Number 1=541-220KGCT-ND, TempCo="200 ppm/C", Tolerance_%=5%, Value2=0.1W, Value_Code=220k
R37: library part CMP-0023232-5, "RES, 66.5 k, 1%, 0.1 W, 0603", Manufacturer=Yageo, Power_W=100mW, Supplier Part Number 1=311-66.5KHRCT-ND, TempCo="100 ppm/C", Tolerance_%=1%, Value2=0.1W, Value_Code=66k5, ValueDisplayed=66.5k
R102 R122: library part CMP-0017255-2, "RES, 0.003, 1%, 1 W, 1206", Manufacturer="Stackpole Electronics Inc", Power_W=1W, Supplier Part Number 1=CSNL1206FT3L00CT-ND, TempCo="50 ppm/C", Tolerance_%=1%, Value_Code=3L000, ValueDisplayed=0.003
R103: library part CMP-0022917-4, "RES, 220 k, 1%, 0.1 W, 0603", Manufacturer=Yageo, Power_W=100mW, Supplier Part Number 1=311-220KHRCT-ND, TempCo="100 ppm/C", Tolerance_%=1%, Value2=0.1W, Value_Code=220k
R104: library part CMP-0022951-5, "RES, 25.5 k, 1%, 0.1 W, 0603", Manufacturer=Yageo, Power_W=100mW, Supplier Part Number 1=311-25.5KHRCT-ND, TempCo="100 ppm/C", Tolerance_%=1%, Value2=0.1W, Value_Code=25k5, ValueDisplayed=25.5k
R106: library part CMP-0022900-4, "RES, 1.00, 1%, 0.1 W, 0603", Manufacturer=Yageo, Power_W=100mW, Supplier Part Number 1=311-1.00HRCT-ND, TempCo="200 ppm/C", Tolerance_%=1%, Value2=0.1W, Value_Code=1R00, ValueDisplayed=1.00
R107: library part CMP-0022913-5, "RES, 21.5 k, 1%, 0.1 W, 0603", Manufacturer=Yageo, Power_W=100mW, Supplier Part Number 1=311-21.5KHRCT-ND, TempCo="100 ppm/C", Tolerance_%=1%, Value2=0.1W, Value_Code=21k5, ValueDisplayed=21.5k
R108: library part CMP-0096703-1, "NTC Thermistor 470k 0603 (1608 Metric)", B Tolerance=3%, Digikey Part Number=495-B57371V2474J060CT-ND, Manufacturer=TDK, Mouser Part Number=871-B57371V2474J060, Operating Temperature Range="-55°C to +125°C", Power_W=180mW, Tolerance_%=5%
